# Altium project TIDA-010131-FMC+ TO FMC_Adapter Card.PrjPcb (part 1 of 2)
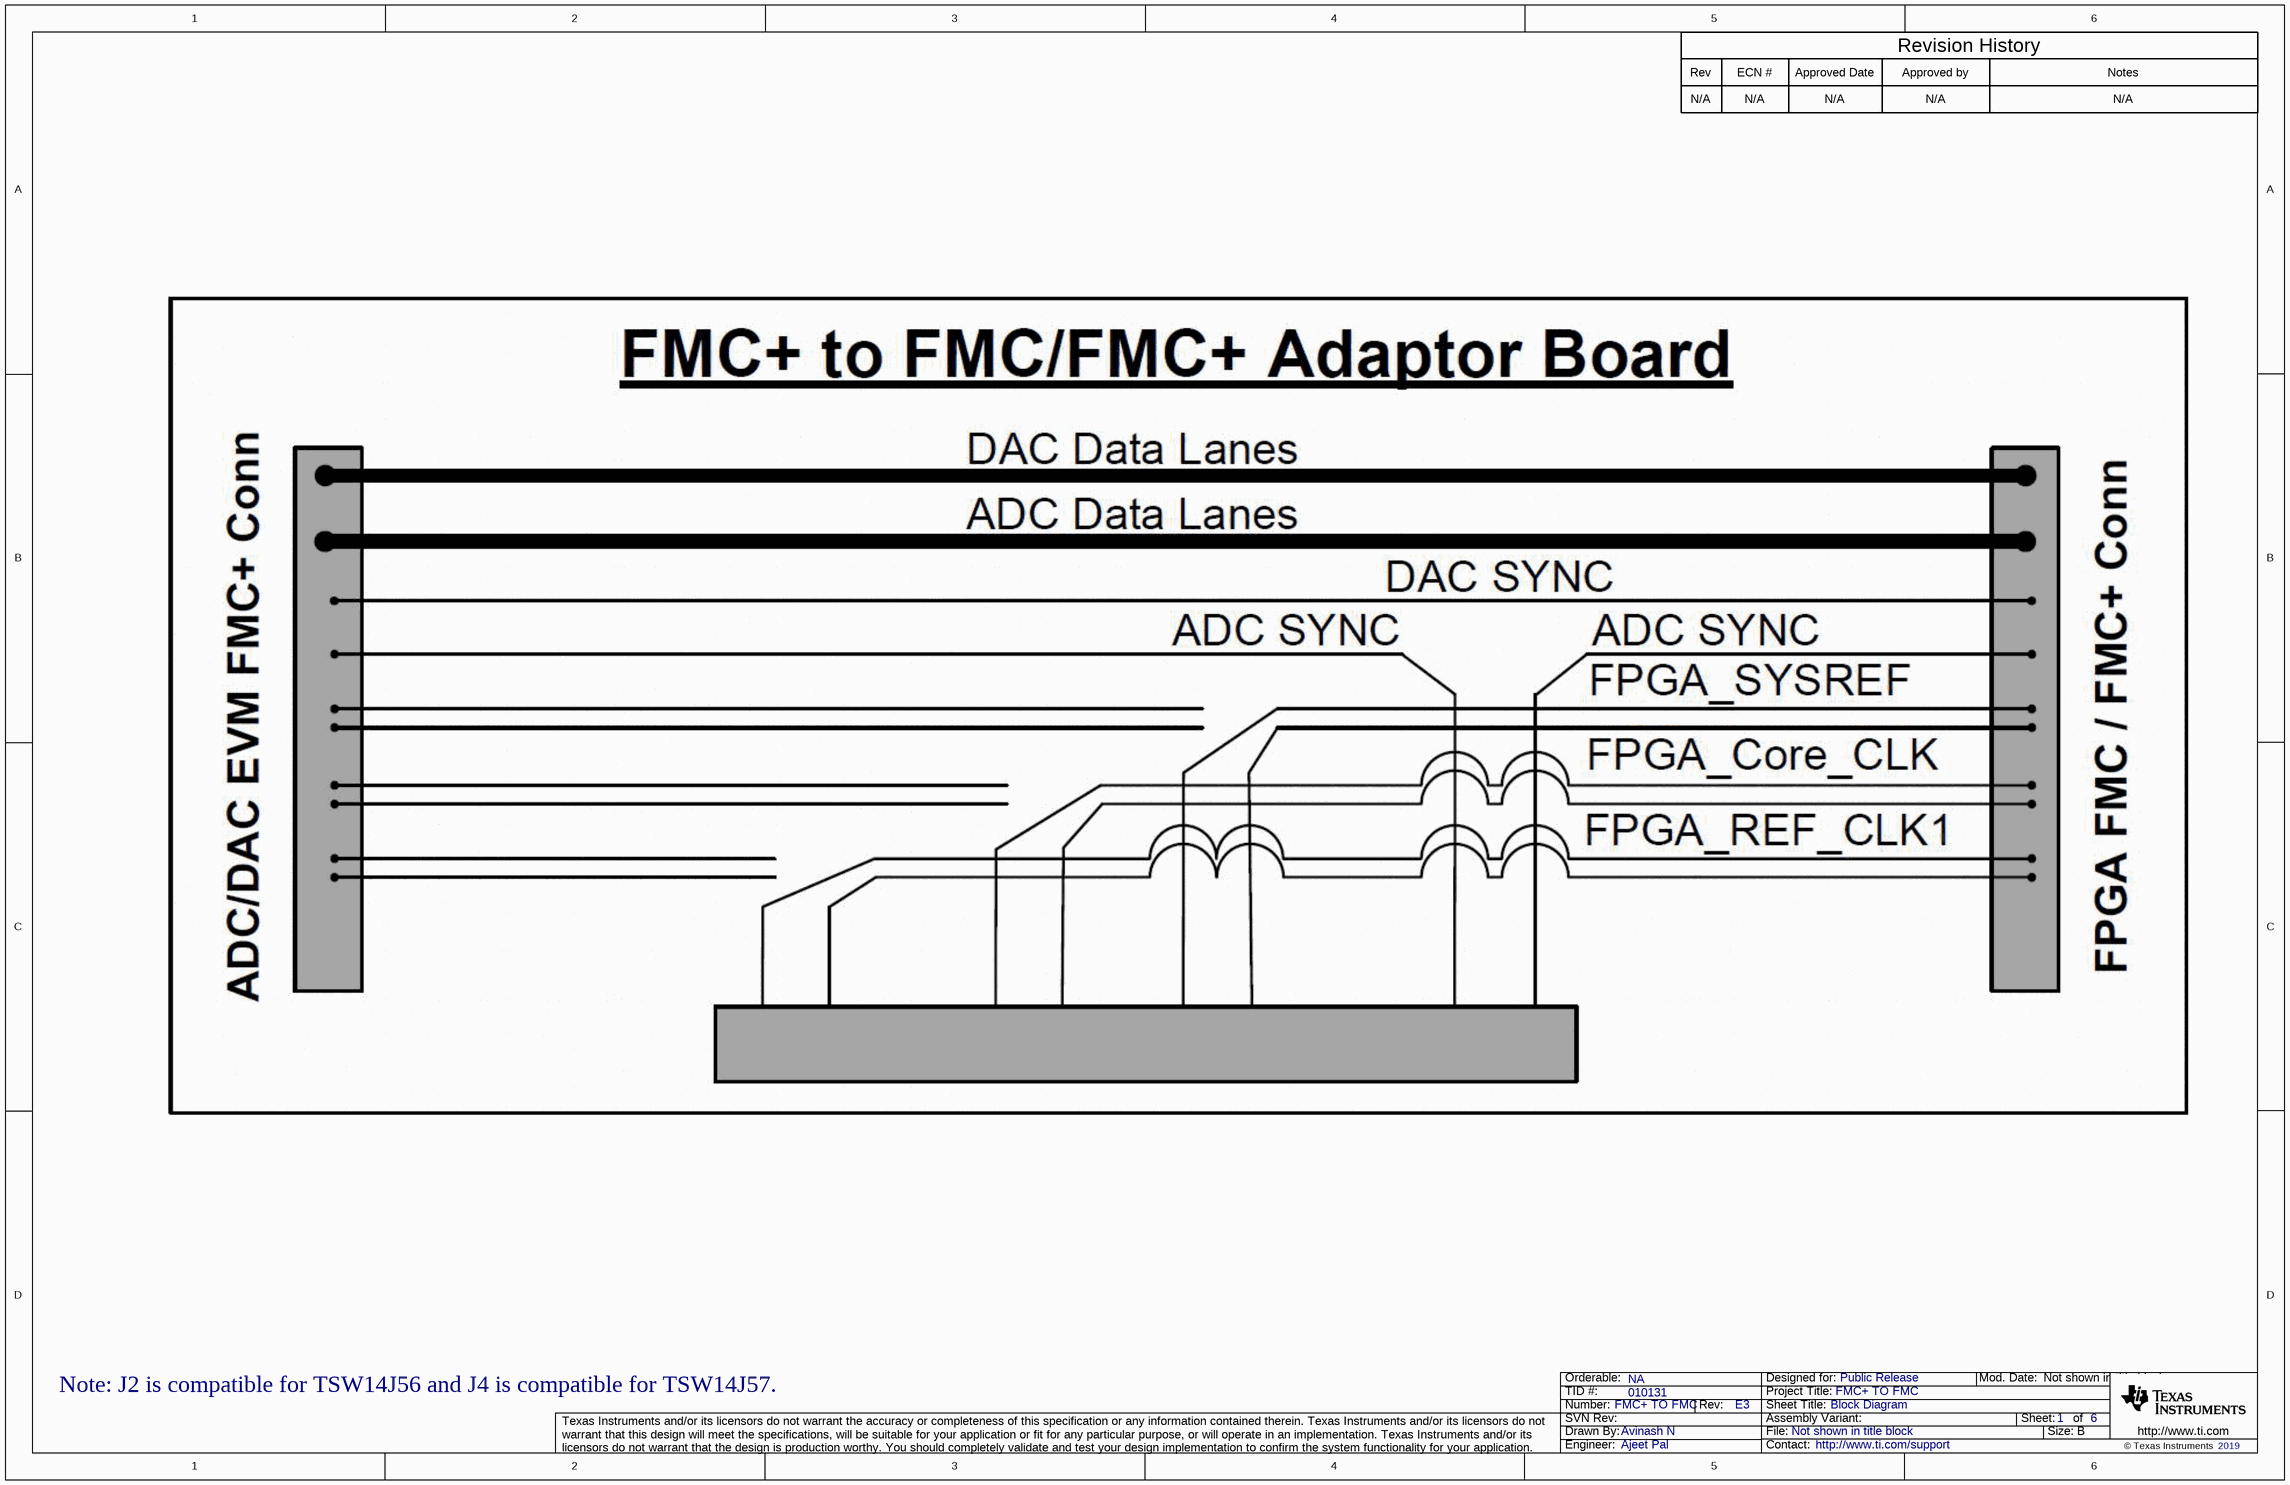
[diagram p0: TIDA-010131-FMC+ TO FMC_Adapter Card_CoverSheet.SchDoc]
CopyrightYear: 2019; EVM_orderable: NA; PCB_Layout: Avinash N; PCB_Rev: E3; PRJ_Customer: Public Release; PRJ_Engineer: Ajeet Pal; PRJ_Number: FMC+ TO FMC; PRJ_Title: FMC+ TO FMC; SCH_Rev: E3; TechSupport: http://www.ti.com/support; TID: 010131
6 sheets, 65 parts. Net scope: global (net labels, ports and power ports of the same name join across sheets).
Board file: TIDA-010131-FMC+ TO FMC_Adapter Card.PcbDoc
Sheets:
  TIDA-010131-FMC+ TO FMC_Adapter Card_CoverSheet.SchDoc
  TIDA-010131-FMC+ TO FMC_Adapter Card_Sheet1.SchDoc
  TIDA-010131-FMC+ TO FMC_Adapter Card_Sheet2.SchDoc
  TIDA-010131-FMC+ TO FMC_Adapter Card_Sheet3.SchDoc
  TIDA-010131-FMC+ TO FMC_Adapter Card_Sheet4.SchDoc
  TIDA-010131-FMC+ TO FMC_Adapter Card_Hardware.SchDoc

## Sheet TIDA-010131-FMC+ TO FMC_Adapter Card_CoverSheet.SchDoc: Block Diagram
size 431 x 279 mm; Date: Not shown in title block; ApprovedBy: Not shown in title block; CheckedBy: Not shown in title block; Author: Not shown in title block; CompanyName: Not shown in title block; DrawnBy: Avinash N; Engineer: Not shown in title block; Organization: Not shown in title block; Address1: Not shown in title block; Address2: Not shown in title block; Address3: Not shown in title block; Address4: Not shown in title block; DocumentNumber: 1; Revision: Use project parameter SCH_Rev; SheetNumber: 1; SheetTotal: 6; PageSetup: Record=PageOptions¦CenterHorizontal=True¦CenterVertical=True¦PrintScale=1.00¦XCorrection=1.00¦YCorrection=1.00¦PrintKind=0¦BorderSize=5000000¦LeftOffset=0¦BottomOffset=0¦Orientation=2¦PaperLength=1000¦PaperWidth=1000¦Scale=100¦PaperSource=15¦PrintQuality=600¦MediaType=1¦DitherType=10¦PaperKind=Letter¦PrintScaleMode=1

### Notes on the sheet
- Rev
- N/A
- ECN #
- Approved Date
- Approved by
- Revision History
- Notes
- Note: J2 is compatible for TSW14J56 and J4 is compatible for TSW14J57.

## Sheet TIDA-010131-FMC+ TO FMC_Adapter Card_Sheet1.SchDoc
size 431 x 279 mm; Date: Not shown in title block; ApprovedBy: Not shown in title block; CheckedBy: Not shown in title block; Author: Not shown in title block; CompanyName: Not shown in title block; DrawnBy: Avinash N; Engineer: Not shown in title block; Organization: Not shown in title block; Address1: Not shown in title block; Address2: Not shown in title block; Address3: Not shown in title block; Address4: Not shown in title block; DocumentNumber: 2; Revision: Use project parameter SCH_Rev; SheetNumber: 2; SheetTotal: 6; PageSetup: Record=PageOptions¦CenterHorizontal=True¦CenterVertical=True¦PrintScale=1.00¦XCorrection=1.00¦YCorrection=1.00¦PrintKind=0¦BorderSize=5000000¦LeftOffset=0¦BottomOffset=0¦Orientation=2¦PaperLength=1000¦PaperWidth=1000¦Scale=100¦PaperSource=15¦PrintQuality=600¦MediaType=1¦DitherType=10¦PaperKind=Letter¦PrintScaleMode=1
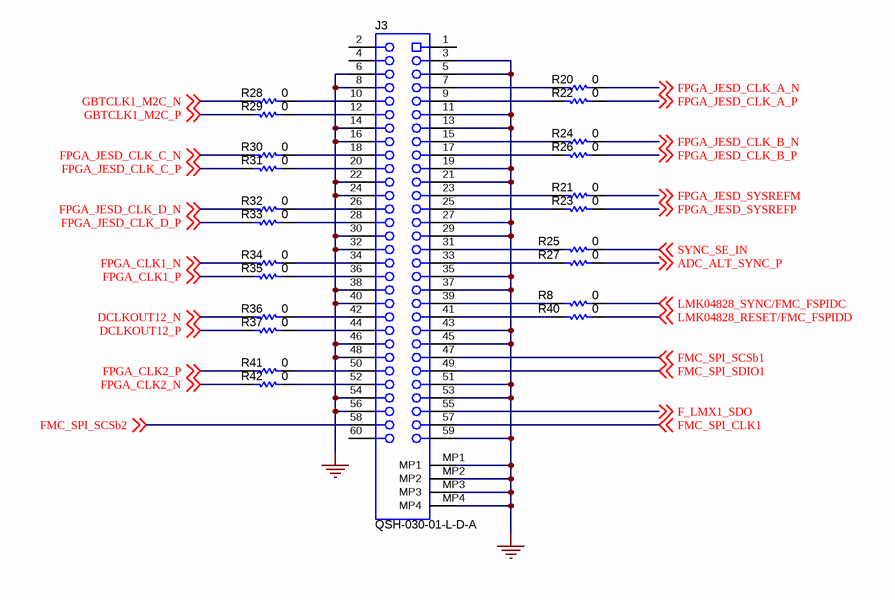
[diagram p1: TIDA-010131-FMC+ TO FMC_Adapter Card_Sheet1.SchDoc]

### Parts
J3  QSH-030-01-L-D-A  [Samtec_QSH-030-01-X-D-A]
R8  ValueDisplayed: 0  [0402]  (hidden comment: CRCW04020000Z0ED)
R20  ValueDisplayed: 0  [0201]  (hidden comment: ERJ-1GN0R00C)
R21  ValueDisplayed: 0  [0201]  (hidden comment: ERJ-1GN0R00C)
R22  ValueDisplayed: 0  [0201]  (hidden comment: ERJ-1GN0R00C)
R23  ValueDisplayed: 0  [0201]  (hidden comment: ERJ-1GN0R00C)
R24  ValueDisplayed: 0  [0201]  (hidden comment: ERJ-1GN0R00C)
R25  ValueDisplayed: 0  [0402]  (hidden comment: CRCW04020000Z0ED)
R26  ValueDisplayed: 0  [0201]  (hidden comment: ERJ-1GN0R00C)
R27  ValueDisplayed: 0  [0402]  (hidden comment: CRCW04020000Z0ED)
R28  ValueDisplayed: 0  [0201]  (hidden comment: ERJ-1GN0R00C)
R29  ValueDisplayed: 0  [0201]  (hidden comment: ERJ-1GN0R00C)
R30  ValueDisplayed: 0  [0201]  (hidden comment: ERJ-1GN0R00C)
R31  ValueDisplayed: 0  [0201]  (hidden comment: ERJ-1GN0R00C)
R32  ValueDisplayed: 0  [0201]  (hidden comment: ERJ-1GN0R00C)
R33  ValueDisplayed: 0  [0201]  (hidden comment: ERJ-1GN0R00C)
R34  ValueDisplayed: 0  [0201]  (hidden comment: ERJ-1GN0R00C)
R35  ValueDisplayed: 0  [0201]  (hidden comment: ERJ-1GN0R00C)
R36  ValueDisplayed: 0  [0201]  (hidden comment: ERJ-1GN0R00C)
R37  ValueDisplayed: 0  [0201]  (hidden comment: ERJ-1GN0R00C)
R40  ValueDisplayed: 0  [0402]  (hidden comment: CRCW04020000Z0ED)
R41  ValueDisplayed: 0  [0201]  (hidden comment: ERJ-1GN0R00C)
R42  ValueDisplayed: 0  [0201]  (hidden comment: ERJ-1GN0R00C)

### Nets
GND: J3.3 J3.5 J3.6 J3.8 J3.11 J3.13 J3.14 J3.16 J3.19 J3.21 J3.22 J3.24 J3.27 J3.29 J3.30 J3.32 J3.35 J3.37 J3.38 J3.40 J3.43 J3.45 J3.46 J3.48 J3.51 J3.53 J3.54 J3.56 J3.59 J3.MP1 J3.MP2 J3.MP3 J3.MP4
ADC_ALT_SYNC_P: R27.1 ; off-sheet ADC_ALT_SYNC_P
DCLKOUT12_N: R36.2 ; off-sheet DCLKOUT12_N
DCLKOUT12_P: R37.2 ; off-sheet DCLKOUT12_P
F_LMX1_SDO: J3.55 ; off-sheet F_LMX1_SDO
FMC_SPI_CLK1: J3.57 ; off-sheet FMC_SPI_CLK1
FMC_SPI_SCSb1: J3.47 ; off-sheet FMC_SPI_SCSb1
FMC_SPI_SCSb2: J3.58 ; off-sheet FMC_SPI_SCSb2
FMC_SPI_SDIO1: J3.49 ; off-sheet FMC_SPI_SDIO1
FPGA_CLK1_N: R34.2 ; off-sheet FPGA_CLK1_N
FPGA_CLK1_P: R35.2 ; off-sheet FPGA_CLK1_P
FPGA_CLK2_N: R42.2 ; off-sheet FPGA_CLK2_N
FPGA_CLK2_P: R41.2 ; off-sheet FPGA_CLK2_P
FPGA_JESD_CLK_A_N: R20.1 ; off-sheet FPGA_JESD_CLK_A_N
FPGA_JESD_CLK_A_P: R22.1 ; off-sheet FPGA_JESD_CLK_A_P
FPGA_JESD_CLK_B_N: R24.1 ; off-sheet FPGA_JESD_CLK_B_N
FPGA_JESD_CLK_B_P: R26.1 ; off-sheet FPGA_JESD_CLK_B_P
FPGA_JESD_CLK_C_N: R30.2 ; off-sheet FPGA_JESD_CLK_C_N
FPGA_JESD_CLK_C_P: R31.2 ; off-sheet FPGA_JESD_CLK_C_P
FPGA_JESD_CLK_D_N: R32.2 ; off-sheet FPGA_JESD_CLK_D_N
FPGA_JESD_CLK_D_P: R33.2 ; off-sheet FPGA_JESD_CLK_D_P
FPGA_JESD_SYSREFM: R21.1 ; off-sheet FPGA_JESD_SYSREFM
FPGA_JESD_SYSREFP: R23.1 ; off-sheet FPGA_JESD_SYSREFP
GBTCLK1_M2C_N: R28.2 ; off-sheet GBTCLK1_M2C_N
GBTCLK1_M2C_P: R29.2 ; off-sheet GBTCLK1_M2C_P
LMK04828_RESET/FMC_FSPIDD: R40.1 ; off-sheet LMK04828_RESET/FMC_FSPIDD
LMK04828_SYNC/FMC_FSPIDC: R8.1 ; off-sheet LMK04828_SYNC/FMC_FSPIDC
SYNC_SE_IN: R25.1 ; off-sheet SYNC_SE_IN
NetJ3_7: J3.7 R20.2
NetJ3_9: J3.9 R22.2
NetJ3_10: J3.10 R28.1
NetJ3_12: J3.12 R29.1
NetJ3_15: J3.15 R24.2
NetJ3_17: J3.17 R26.2
NetJ3_18: J3.18 R30.1
NetJ3_20: J3.20 R31.1
NetJ3_23: J3.23 R21.2
NetJ3_25: J3.25 R23.2
NetJ3_26: J3.26 R32.1
NetJ3_28: J3.28 R33.1
NetJ3_31: J3.31 R25.2
NetJ3_33: J3.33 R27.2
NetJ3_34: J3.34 R34.1
NetJ3_36: J3.36 R35.1
NetJ3_39: J3.39 R8.2
NetJ3_41: J3.41 R40.2
NetJ3_42: J3.42 R36.1
NetJ3_44: J3.44 R37.1
NetJ3_50: J3.50 R41.1
NetJ3_52: J3.52 R42.1

Not connected (* = marked no-connect by the designer): J3 1 2 4 60

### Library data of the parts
J3 = QSH-030-01-L-D-A: Receptacle, 0.5 mm, 30x2, Gold, TH; Manufacturer: Samtec; SymbolCreator: Altium; Pitch_mm: 0.5; Gender: Female; Shrouded: N; Row_Count: 2; RowSpacing_mm: 5.73
R8 R25 R27 R40 = CRCW04020000Z0ED: RES, 0, 5%, 0.063 W, 0402; Manufacturer: Vishay-Dale; CompType: Resistor; Value: 0; Value_Code: 0000; Tolerance_%: 5; Power_W: 0.063; Value2: 0.063W; VDC_V: 50; TempCo: 200 ppm/C; SizeArea_mm2: 0.5; SizeX_mm: 1; SizeZ_mm: 0.6; EIA_Code: E24; U/M: EA; AEC Category: Q200
R20-R24 R26 R28-R37 R41 R42 = ERJ-1GN0R00C: RES, 0, 5%, 0.05 W, AEC-Q200 Grade 0, 0201; Manufacturer: Panasonic; CompType: Resistor; Value: 0; Value_Code: 0000; Tolerance_%: 5; Power_W: 0.05; Value2: 0.05W; TempCo: ppm/C; SizeArea_mm2: 0.18; SizeX_mm: 0.6; SizeY_mm: 0.3; SizeZ_mm: 0.26; EIA_Code: E24; U/M: EA; AEC Category: Q200; AEC Qualified: Y

## Sheet TIDA-010131-FMC+ TO FMC_Adapter Card_Sheet2.SchDoc
size 431 x 279 mm; Date: Not shown in title block; ApprovedBy: Not shown in title block; CheckedBy: Not shown in title block; Author: Not shown in title block; CompanyName: Not shown in title block; DrawnBy: Avinash N; Engineer: Not shown in title block; Organization: Not shown in title block; Address1: Not shown in title block; Address2: Not shown in title block; Address3: Not shown in title block; Address4: Not shown in title block; DocumentNumber: 3; Revision: Use project parameter SCH_Rev; SheetNumber: 3; SheetTotal: 6; PageSetup: Record=PageOptions¦CenterHorizontal=True¦CenterVertical=True¦PrintScale=0.64¦XCorrection=1.00¦YCorrection=1.00¦PrintKind=0¦BorderSize=5000000¦LeftOffset=0¦BottomOffset=0¦Orientation=2¦PaperLength=1000¦PaperWidth=1000¦Scale=100¦PaperSource=15¦PrintQuality=600¦MediaType=1¦DitherType=10¦PrintScaleMode=1¦PaperKind=Letter
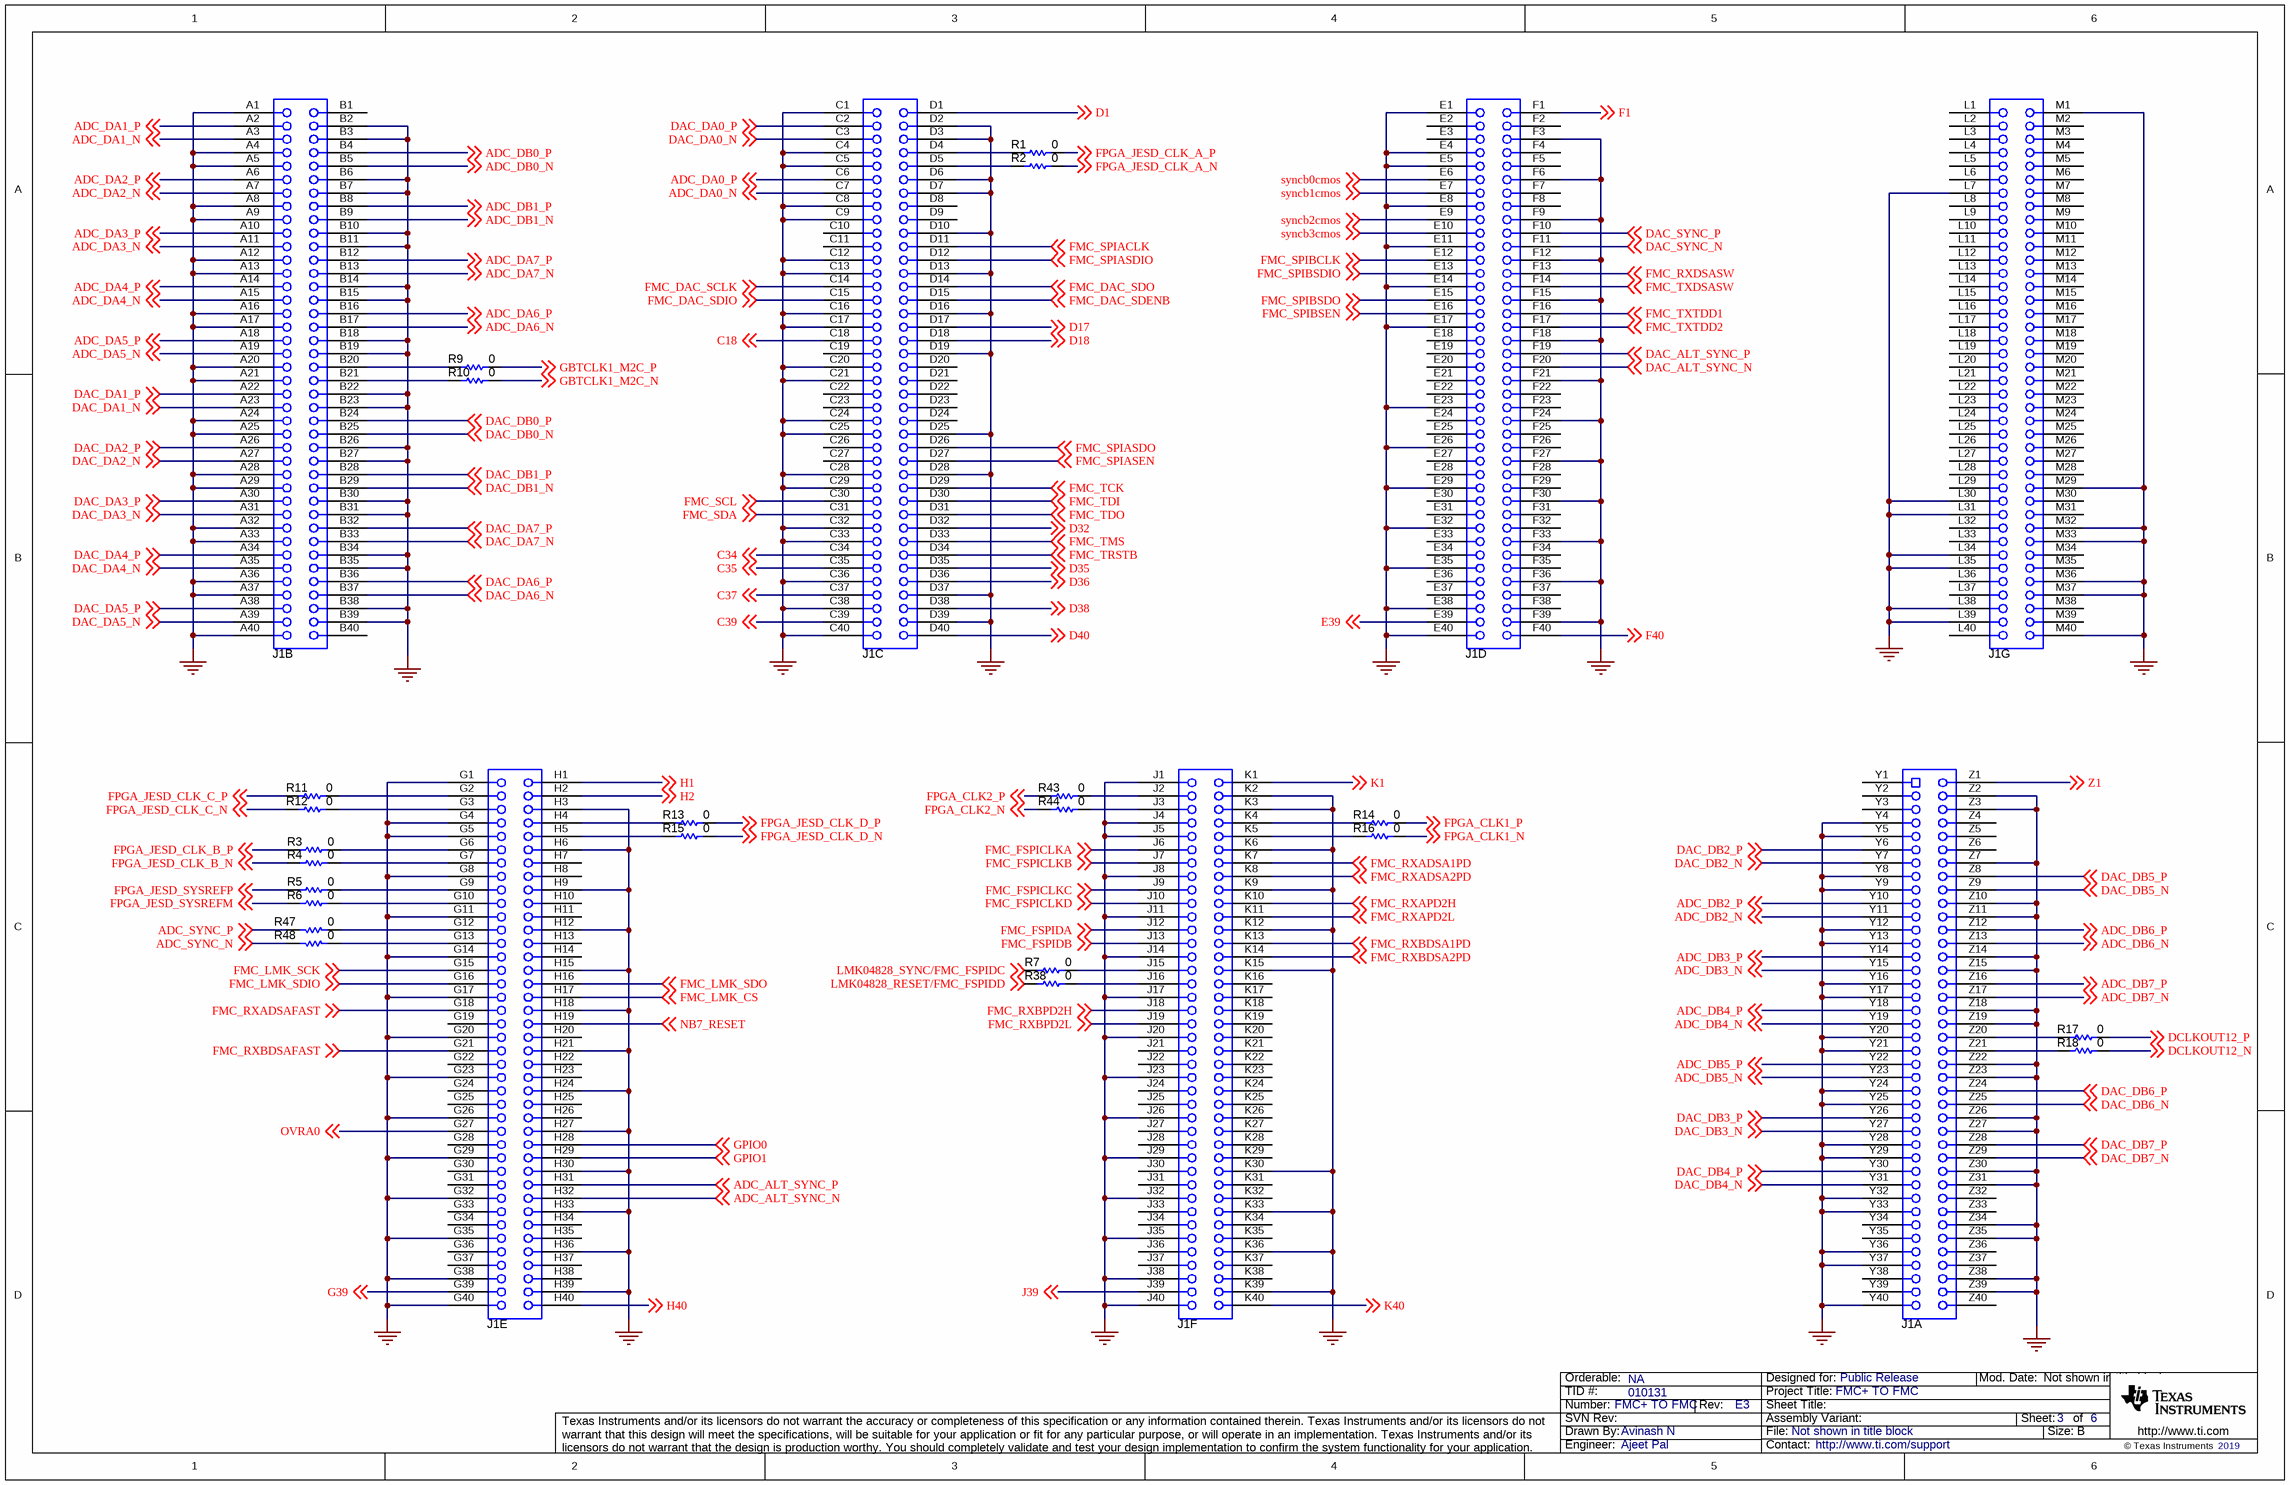
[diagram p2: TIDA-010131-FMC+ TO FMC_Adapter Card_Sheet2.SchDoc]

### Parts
J1  ASP-184329-01  [Samtec_ASP-184329-01]  (value not drawn)  (parts A,B,C,D,E,F,G of 7)
R1  ValueDisplayed: 0  [0201]  (hidden comment: ERJ-1GN0R00C)
R2  ValueDisplayed: 0  [0201]  (hidden comment: ERJ-1GN0R00C)
R3  ValueDisplayed: 0  [0201]  (hidden comment: ERJ-1GN0R00C)
R4  ValueDisplayed: 0  [0201]  (hidden comment: ERJ-1GN0R00C)
R5  ValueDisplayed: 0  [0201]  (hidden comment: ERJ-1GN0R00C)
R6  ValueDisplayed: 0  [0201]  (hidden comment: ERJ-1GN0R00C)
R7  ValueDisplayed: 0  [0402]  (hidden comment: CRCW04020000Z0ED)
R9  ValueDisplayed: 0  [0201]  (hidden comment: ERJ-1GN0R00C)
R10  ValueDisplayed: 0  [0201]  (hidden comment: ERJ-1GN0R00C)
R11  ValueDisplayed: 0  [0201]  (hidden comment: ERJ-1GN0R00C)
R12  ValueDisplayed: 0  [0201]  (hidden comment: ERJ-1GN0R00C)
R13  ValueDisplayed: 0  [0201]  (hidden comment: ERJ-1GN0R00C)
R14  ValueDisplayed: 0  [0201]  (hidden comment: ERJ-1GN0R00C)
R15  ValueDisplayed: 0  [0201]  (hidden comment: ERJ-1GN0R00C)
R16  ValueDisplayed: 0  [0201]  (hidden comment: ERJ-1GN0R00C)
R17  ValueDisplayed: 0  [0201]  (hidden comment: ERJ-1GN0R00C)
R18  ValueDisplayed: 0  [0201]  (hidden comment: ERJ-1GN0R00C)
R38  ValueDisplayed: 0  [0402]  (hidden comment: CRCW04020000Z0ED)
R43  ValueDisplayed: 0  [0201]  (hidden comment: ERJ-1GN0R00C)
R44  ValueDisplayed: 0  [0201]  (hidden comment: ERJ-1GN0R00C)
R47  ValueDisplayed: 0  [0402]  (hidden comment: CRCW04020000Z0ED)
R48  ValueDisplayed: 0  [0402]  (hidden comment: CRCW04020000Z0ED)

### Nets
GND: J1.A1 J1.A4 J1.A5 J1.A8 J1.A9 J1.A12 J1.A13 J1.A16 J1.A17 J1.A20 J1.A21 J1.A24 J1.A25 J1.A28 J1.A29 J1.A32 J1.A33 J1.A36 J1.A37 J1.A40 J1.B2 J1.B3 J1.B6 J1.B7 J1.B10 J1.B11 J1.B14 J1.B15 J1.B18 J1.B19 J1.B22 J1.B23 J1.B26 J1.B27 J1.B30 J1.B31 J1.B34 J1.B35 J1.B38 J1.B39 J1.C1 J1.C4 J1.C5 J1.C8 J1.C9 J1.C12 J1.C13 J1.C16 J1.C17 J1.C20 J1.C21 J1.C24 J1.C25 J1.C28 J1.C29 J1.C32 J1.C33 J1.C36 J1.C38 J1.C40 J1.D2 J1.D3 J1.D6 J1.D7 J1.D10 J1.D13 J1.D16 J1.D19 J1.D25 J1.D28 J1.D37 J1.D39 J1.E1 J1.E4 J1.E5 J1.E8 J1.E11 J1.E14 J1.E17 J1.E23 J1.E26 J1.E29 J1.E32 J1.E35 J1.E38 J1.E40 J1.F3 J1.F6 J1.F9 J1.F12 J1.F15 J1.F18 J1.F21 J1.F24 J1.F27 J1.F30 J1.F33 J1.F36 J1.F39 J1.G1 J1.G4 J1.G5 J1.G8 J1.G11 J1.G14 J1.G17 J1.G20 J1.G23 J1.G26 J1.G29 J1.G32 J1.G35 J1.G38 J1.G40 J1.H3 J1.H6 J1.H9 J1.H12 J1.H15 J1.H18 J1.H21 J1.H24 J1.H27 J1.H30 J1.H33 J1.H36 J1.H39 J1.J1 J1.J4 J1.J5 J1.J8 J1.J11 J1.J14 J1.J17 J1.J20 J1.J23 J1.J26 J1.J29 J1.J32 J1.J35 J1.J38 J1.J40 J1.K2 J1.K3 J1.K6 J1.K9 J1.K12 J1.K15 J1.K30 J1.K33 J1.K36 J1.K39 J1.L7 J1.L30 J1.L31 J1.L34 J1.L35 J1.L38 J1.L39 J1.M1 J1.M29 J1.M32 J1.M33 J1.M36 J1.M37 J1.M40 J1.Y4 J1.Y5 J1.Y8 J1.Y9 J1.Y12 J1.Y13 J1.Y16 J1.Y17 J1.Y20 J1.Y21 J1.Y24 J1.Y25 J1.Y28 J1.Y29 J1.Y32 J1.Y33 J1.Y36 J1.Y37 J1.Y40 J1.Z2 J1.Z3 J1.Z7 J1.Z10 J1.Z11 J1.Z14 J1.Z15 J1.Z18 J1.Z19 J1.Z22 J1.Z23 J1.Z26 J1.Z27 J1.Z30 J1.Z31 J1.Z34 J1.Z35 J1.Z38 J1.Z39
ADC_ALT_SYNC_N: J1.H32 ; off-sheet ADC_ALT_SYNC_N
ADC_ALT_SYNC_P: J1.H31 ; off-sheet ADC_ALT_SYNC_P
ADC_DA0_N: J1.C7 ; off-sheet ADC_DA0_N
ADC_DA0_P: J1.C6 ; off-sheet ADC_DA0_P
ADC_DA1_N: J1.A3 ; off-sheet ADC_DA1_N
ADC_DA1_P: J1.A2 ; off-sheet ADC_DA1_P
ADC_DA2_N: J1.A7 ; off-sheet ADC_DA2_N
ADC_DA2_P: J1.A6 ; off-sheet ADC_DA2_P
ADC_DA3_N: J1.A11 ; off-sheet ADC_DA3_N
ADC_DA3_P: J1.A10 ; off-sheet ADC_DA3_P
ADC_DA4_N: J1.A15 ; off-sheet ADC_DA4_N
ADC_DA4_P: J1.A14 ; off-sheet ADC_DA4_P
ADC_DA5_N: J1.A19 ; off-sheet ADC_DA5_N
ADC_DA5_P: J1.A18 ; off-sheet ADC_DA5_P
ADC_DA6_N: J1.B17 ; off-sheet ADC_DA6_N
ADC_DA6_P: J1.B16 ; off-sheet ADC_DA6_P
ADC_DA7_N: J1.B13 ; off-sheet ADC_DA7_N
ADC_DA7_P: J1.B12 ; off-sheet ADC_DA7_P
ADC_DB0_N: J1.B5 ; off-sheet ADC_DB0_N
ADC_DB0_P: J1.B4 ; off-sheet ADC_DB0_P
ADC_DB1_N: J1.B9 ; off-sheet ADC_DB1_N
ADC_DB1_P: J1.B8 ; off-sheet ADC_DB1_P
ADC_DB2_N: J1.Y11 ; off-sheet ADC_DB2_N
ADC_DB2_P: J1.Y10 ; off-sheet ADC_DB2_P
ADC_DB3_N: J1.Y15 ; off-sheet ADC_DB3_N
ADC_DB3_P: J1.Y14 ; off-sheet ADC_DB3_P
ADC_DB4_N: J1.Y19 ; off-sheet ADC_DB4_N
ADC_DB4_P: J1.Y18 ; off-sheet ADC_DB4_P
ADC_DB5_N: J1.Y23 ; off-sheet ADC_DB5_N
ADC_DB5_P: J1.Y22 ; off-sheet ADC_DB5_P
ADC_DB6_N: J1.Z13 ; off-sheet ADC_DB6_N
ADC_DB6_P: J1.Z12 ; off-sheet ADC_DB6_P
ADC_DB7_N: J1.Z17 ; off-sheet ADC_DB7_N
ADC_DB7_P: J1.Z16 ; off-sheet ADC_DB7_P
ADC_SYNC_N: R48.2 ; off-sheet ADC_SYNC_N
ADC_SYNC_P: R47.2 ; off-sheet ADC_SYNC_P
C18: J1.C18 ; off-sheet C18
C34: J1.C34 ; off-sheet C34
C35: J1.C35 ; off-sheet C35
C37: J1.C37 ; off-sheet C37
C39: J1.C39 ; off-sheet C39
D1: J1.D1 ; off-sheet D1
D17: J1.D17 ; off-sheet D17
D18: J1.D18 ; off-sheet D18
D32: J1.D32 ; off-sheet D32
D35: J1.D35 ; off-sheet D35
D36: J1.D36 ; off-sheet D36
D38: J1.D38 ; off-sheet D38
D40: J1.D40 ; off-sheet D40
DAC_ALT_SYNC_N: J1.F20 ; off-sheet DAC_ALT_SYNC_N
DAC_ALT_SYNC_P: J1.F19 ; off-sheet DAC_ALT_SYNC_P
DAC_DA0_N: J1.C3 ; off-sheet DAC_DA0_N
DAC_DA0_P: J1.C2 ; off-sheet DAC_DA0_P
DAC_DA1_N: J1.A23 ; off-sheet DAC_DA1_N
DAC_DA1_P: J1.A22 ; off-sheet DAC_DA1_P
DAC_DA2_N: J1.A27 ; off-sheet DAC_DA2_N
DAC_DA2_P: J1.A26 ; off-sheet DAC_DA2_P
DAC_DA3_N: J1.A31 ; off-sheet DAC_DA3_N
DAC_DA3_P: J1.A30 ; off-sheet DAC_DA3_P
DAC_DA4_N: J1.A35 ; off-sheet DAC_DA4_N
DAC_DA4_P: J1.A34 ; off-sheet DAC_DA4_P
DAC_DA5_N: J1.A39 ; off-sheet DAC_DA5_N
DAC_DA5_P: J1.A38 ; off-sheet DAC_DA5_P
DAC_DA6_N: J1.B37 ; off-sheet DAC_DA6_N
DAC_DA6_P: J1.B36 ; off-sheet DAC_DA6_P
DAC_DA7_N: J1.B33 ; off-sheet DAC_DA7_N
DAC_DA7_P: J1.B32 ; off-sheet DAC_DA7_P
DAC_DB0_N: J1.B25 ; off-sheet DAC_DB0_N
DAC_DB0_P: J1.B24 ; off-sheet DAC_DB0_P
DAC_DB1_N: J1.B29 ; off-sheet DAC_DB1_N
DAC_DB1_P: J1.B28 ; off-sheet DAC_DB1_P
DAC_DB2_N: J1.Y7 ; off-sheet DAC_DB2_N
DAC_DB2_P: J1.Y6 ; off-sheet DAC_DB2_P
DAC_DB3_N: J1.Y27 ; off-sheet DAC_DB3_N
DAC_DB3_P: J1.Y26 ; off-sheet DAC_DB3_P
DAC_DB4_N: J1.Y31 ; off-sheet DAC_DB4_N
DAC_DB4_P: J1.Y30 ; off-sheet DAC_DB4_P
DAC_DB5_N: J1.Z9 ; off-sheet DAC_DB5_N
DAC_DB5_P: J1.Z8 ; off-sheet DAC_DB5_P
DAC_DB6_N: J1.Z25 ; off-sheet DAC_DB6_N
DAC_DB6_P: J1.Z24 ; off-sheet DAC_DB6_P
DAC_DB7_N: J1.Z29 ; off-sheet DAC_DB7_N
DAC_DB7_P: J1.Z28 ; off-sheet DAC_DB7_P
DAC_SYNC_N: J1.F11 ; off-sheet DAC_SYNC_N
DAC_SYNC_P: J1.F10 ; off-sheet DAC_SYNC_P
DCLKOUT12_N: R18.1 ; off-sheet DCLKOUT12_N
DCLKOUT12_P: R17.1 ; off-sheet DCLKOUT12_P
E39: J1.E39 ; off-sheet E39
F1: J1.F1 ; off-sheet F1
F40: J1.F40 ; off-sheet F40
FMC_DAC_SCLK: J1.C14 ; off-sheet FMC_DAC_SCLK
FMC_DAC_SDENB: J1.D15 ; off-sheet FMC_DAC_SDENB
FMC_DAC_SDIO: J1.C15 ; off-sheet FMC_DAC_SDIO
FMC_DAC_SDO: J1.D14 ; off-sheet FMC_DAC_SDO
FMC_FSPICLKA: J1.J6 ; off-sheet FMC_FSPICLKA
FMC_FSPICLKB: J1.J7 ; off-sheet FMC_FSPICLKB
FMC_FSPICLKC: J1.J9 ; off-sheet FMC_FSPICLKC
FMC_FSPICLKD: J1.J10 ; off-sheet FMC_FSPICLKD
FMC_FSPIDA: J1.J12 ; off-sheet FMC_FSPIDA
FMC_FSPIDB: J1.J13 ; off-sheet FMC_FSPIDB
FMC_LMK_CS: J1.H17 ; off-sheet FMC_LMK_CS
FMC_LMK_SCK: J1.G15 ; off-sheet FMC_LMK_SCK
FMC_LMK_SDIO: J1.G16 ; off-sheet FMC_LMK_SDIO
FMC_LMK_SDO: J1.H16 ; off-sheet FMC_LMK_SDO
FMC_RXADSA1PD: J1.K7 ; off-sheet FMC_RXADSA1PD
FMC_RXADSA2PD: J1.K8 ; off-sheet FMC_RXADSA2PD
FMC_RXADSAFAST: J1.G18 ; off-sheet FMC_RXADSAFAST
FMC_RXAPD2H: J1.K10 ; off-sheet FMC_RXAPD2H
FMC_RXAPD2L: J1.K11 ; off-sheet FMC_RXAPD2L
FMC_RXBDSA1PD: J1.K13 ; off-sheet FMC_RXBDSA1PD
FMC_RXBDSA2PD: J1.K14 ; off-sheet FMC_RXBDSA2PD
FMC_RXBDSAFAST: J1.G21 ; off-sheet FMC_RXBDSAFAST
FMC_RXBPD2H: J1.J18 ; off-sheet FMC_RXBPD2H
FMC_RXBPD2L: J1.J19 ; off-sheet FMC_RXBPD2L
FMC_RXDSASW: J1.F13 ; off-sheet FMC_RXDSASW
FMC_SCL: J1.C30 ; off-sheet FMC_SCL
FMC_SDA: J1.C31 ; off-sheet FMC_SDA
FMC_SPIACLK: J1.D11 ; off-sheet FMC_SPIACLK
FMC_SPIASDIO: J1.D12 ; off-sheet FMC_SPIASDIO
FMC_SPIASDO: J1.D26 ; off-sheet FMC_SPIASDO
FMC_SPIASEN: J1.D27 ; off-sheet FMC_SPIASEN
FMC_SPIBCLK: J1.E12 ; off-sheet FMC_SPIBCLK
FMC_SPIBSDIO: J1.E13 ; off-sheet FMC_SPIBSDIO
FMC_SPIBSDO: J1.E15 ; off-sheet FMC_SPIBSDO
FMC_SPIBSEN: J1.E16 ; off-sheet FMC_SPIBSEN
FMC_TCK: J1.D29 ; off-sheet FMC_TCK
FMC_TDI: J1.D30 ; off-sheet FMC_TDI
FMC_TDO: J1.D31 ; off-sheet FMC_TDO
FMC_TMS: J1.D33 ; off-sheet FMC_TMS
FMC_TRSTB: J1.D34 ; off-sheet FMC_TRSTB
FMC_TXDSASW: J1.F14 ; off-sheet FMC_TXDSASW
FMC_TXTDD1: J1.F16 ; off-sheet FMC_TXTDD1
FMC_TXTDD2: J1.F17 ; off-sheet FMC_TXTDD2
FPGA_CLK1_N: R16.1 ; off-sheet FPGA_CLK1_N
FPGA_CLK1_P: R14.1 ; off-sheet FPGA_CLK1_P
FPGA_CLK2_N: R44.2 ; off-sheet FPGA_CLK2_N
FPGA_CLK2_P: R43.2 ; off-sheet FPGA_CLK2_P
FPGA_JESD_CLK_A_N: R2.1 ; off-sheet FPGA_JESD_CLK_A_N
FPGA_JESD_CLK_A_P: R1.1 ; off-sheet FPGA_JESD_CLK_A_P
FPGA_JESD_CLK_B_N: R4.2 ; off-sheet FPGA_JESD_CLK_B_N
FPGA_JESD_CLK_B_P: R3.2 ; off-sheet FPGA_JESD_CLK_B_P
FPGA_JESD_CLK_C_N: R12.2 ; off-sheet FPGA_JESD_CLK_C_N
FPGA_JESD_CLK_C_P: R11.2 ; off-sheet FPGA_JESD_CLK_C_P
FPGA_JESD_CLK_D_N: R15.1 ; off-sheet FPGA_JESD_CLK_D_N
FPGA_JESD_CLK_D_P: R13.1 ; off-sheet FPGA_JESD_CLK_D_P
FPGA_JESD_SYSREFM: R6.2 ; off-sheet FPGA_JESD_SYSREFM
FPGA_JESD_SYSREFP: R5.2 ; off-sheet FPGA_JESD_SYSREFP
G39: J1.G39 ; off-sheet G39
GBTCLK1_M2C_N: R10.1 ; off-sheet GBTCLK1_M2C_N
GBTCLK1_M2C_P: R9.1 ; off-sheet GBTCLK1_M2C_P
GPIO0: J1.H28 ; off-sheet GPIO0
GPIO1: J1.H29 ; off-sheet GPIO1
H1: J1.H1 ; off-sheet H1
H2: J1.H2 ; off-sheet H2
H40: J1.H40 ; off-sheet H40
J39: J1.J39 ; off-sheet J39
K1: J1.K1 ; off-sheet K1
K40: J1.K40 ; off-sheet K40
LMK04828_RESET/FMC_FSPIDD: R38.2 ; off-sheet LMK04828_RESET/FMC_FSPIDD
LMK04828_SYNC/FMC_FSPIDC: R7.2 ; off-sheet LMK04828_SYNC/FMC_FSPIDC
NB7_RESET: J1.H19 ; off-sheet NB7_RESET
OVRA0: J1.G27 ; off-sheet OVRA0
syncb0cmos: J1.E6 ; off-sheet syncb0cmos
syncb1cmos: J1.E7 ; off-sheet syncb1cmos
syncb2cmos: J1.E9 ; off-sheet syncb2cmos
syncb3cmos: J1.E10 ; off-sheet syncb3cmos
Z1: J1.Z1 ; off-sheet Z1
NetJ1_B20: J1.B20 R9.2
NetJ1_B21: J1.B21 R10.2
NetJ1_D4: J1.D4 R1.2
NetJ1_D5: J1.D5 R2.2
NetJ1_G2: J1.G2 R11.1
NetJ1_G3: J1.G3 R12.1
NetJ1_G6: J1.G6 R3.1
NetJ1_G7: J1.G7 R4.1
NetJ1_G9: J1.G9 R5.1
NetJ1_G10: J1.G10 R6.1
NetJ1_G12: J1.G12 R47.1
NetJ1_G13: J1.G13 R48.1
NetJ1_H4: J1.H4 R13.2
NetJ1_H5: J1.H5 R15.2
NetJ1_J2: J1.J2 R43.1
NetJ1_J3: J1.J3 R44.1
NetJ1_J15: J1.J15 R7.1
NetJ1_J16: J1.J16 R38.1
NetJ1_K4: J1.K4 R14.2
NetJ1_K5: J1.K5 R16.2
NetJ1_Z20: J1.Z20 R17.2
NetJ1_Z21: J1.Z21 R18.2

Not connected (* = marked no-connect by the designer): J1 B1 B40 C10 C11 C19 C22 C23 C26 C27 D8 D9 D20 D21 D22 D23 D24 E2 E3 E18 E19 E20 E21 E22 E24 E25 E27 E28 E30 E31 E33 E34 E36 E37 F2 F4 F5 F7 F8 F22 F23 F25 F26 F28 F29 F31 F32 F34 F35 F37 F38 G19 G22 G24 G25 G28 G30 G31 G33 G34 G36 G37 H7 H8 H10 H11 H13 H14 H20 H22 H23 H25 H26 H34 H35 H37 H38 J21 J22 J24 J25 J27 J28 J30 J31 J33 J34 J36 J37 K16 K17 K18 K19 K20 K21 K22 K23 K24 K25 K26 K27 K28 K29 K31 K32 K34 K35 K37 K38 L1 L2 L3 L4 L5 L6 L8 L9 L10 L11 L12 L13 L14 L15 L16 L17 L18 L19 L20 L21 L22 L23 L24 L25 L26 L27 L28 L29 L32 L33 L36 L37 L40 M2 M3 M4 M5 M6 M7 M8 M9 M10 M11 M12 M13 M14 M15 M16 M17 M18 M19 M20 M21 M22 M23 M24 M25 M26 M27 M28 M30 M31 M34 M35 M38 M39 Y1 Y2 Y3 Y34 Y35 Y38 Y39 Z4 Z5 Z6 Z32 Z33 Z36 Z37 Z40

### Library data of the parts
J1 = ASP-184329-01: Socket, 50 mil, 40x14, Gold, SMT; Manufacturer: Samtec; SymbolCreator: Altium; Pitch_mm: 0.5; Gender: Female; Row_Count: 14
R1-R6 R9-R18 R43 R44 = ERJ-1GN0R00C: as R20 on sheet TIDA-010131-FMC+ TO FMC_Adapter Card_Sheet1
R7 R38 R47 R48 = CRCW04020000Z0ED: as R8 on sheet TIDA-010131-FMC+ TO FMC_Adapter Card_Sheet1

## Sheet TIDA-010131-FMC+ TO FMC_Adapter Card_Sheet3.SchDoc
size 431 x 279 mm; Date: Not shown in title block; ApprovedBy: Not shown in title block; CheckedBy: Not shown in title block; Author: Not shown in title block; CompanyName: Not shown in title block; DrawnBy: Avinash N; Engineer: Not shown in title block; Organization: Not shown in title block; Address1: Not shown in title block; Address2: Not shown in title block; Address3: Not shown in title block; Address4: Not shown in title block; DocumentNumber: 4; Revision: Use project parameter SCH_Rev; SheetNumber: 4; SheetTotal: 6; PageSetup: Record=PageOptions¦CenterHorizontal=True¦CenterVertical=True¦PrintScale=1.00¦XCorrection=1.00¦YCorrection=1.00¦PrintKind=0¦BorderSize=5000000¦LeftOffset=0¦BottomOffset=0¦Orientation=2¦PaperLength=1000¦PaperWidth=1000¦Scale=100¦PaperSource=15¦PrintQuality=600¦MediaType=1¦DitherType=10¦PaperKind=Letter¦PrintScaleMode=1
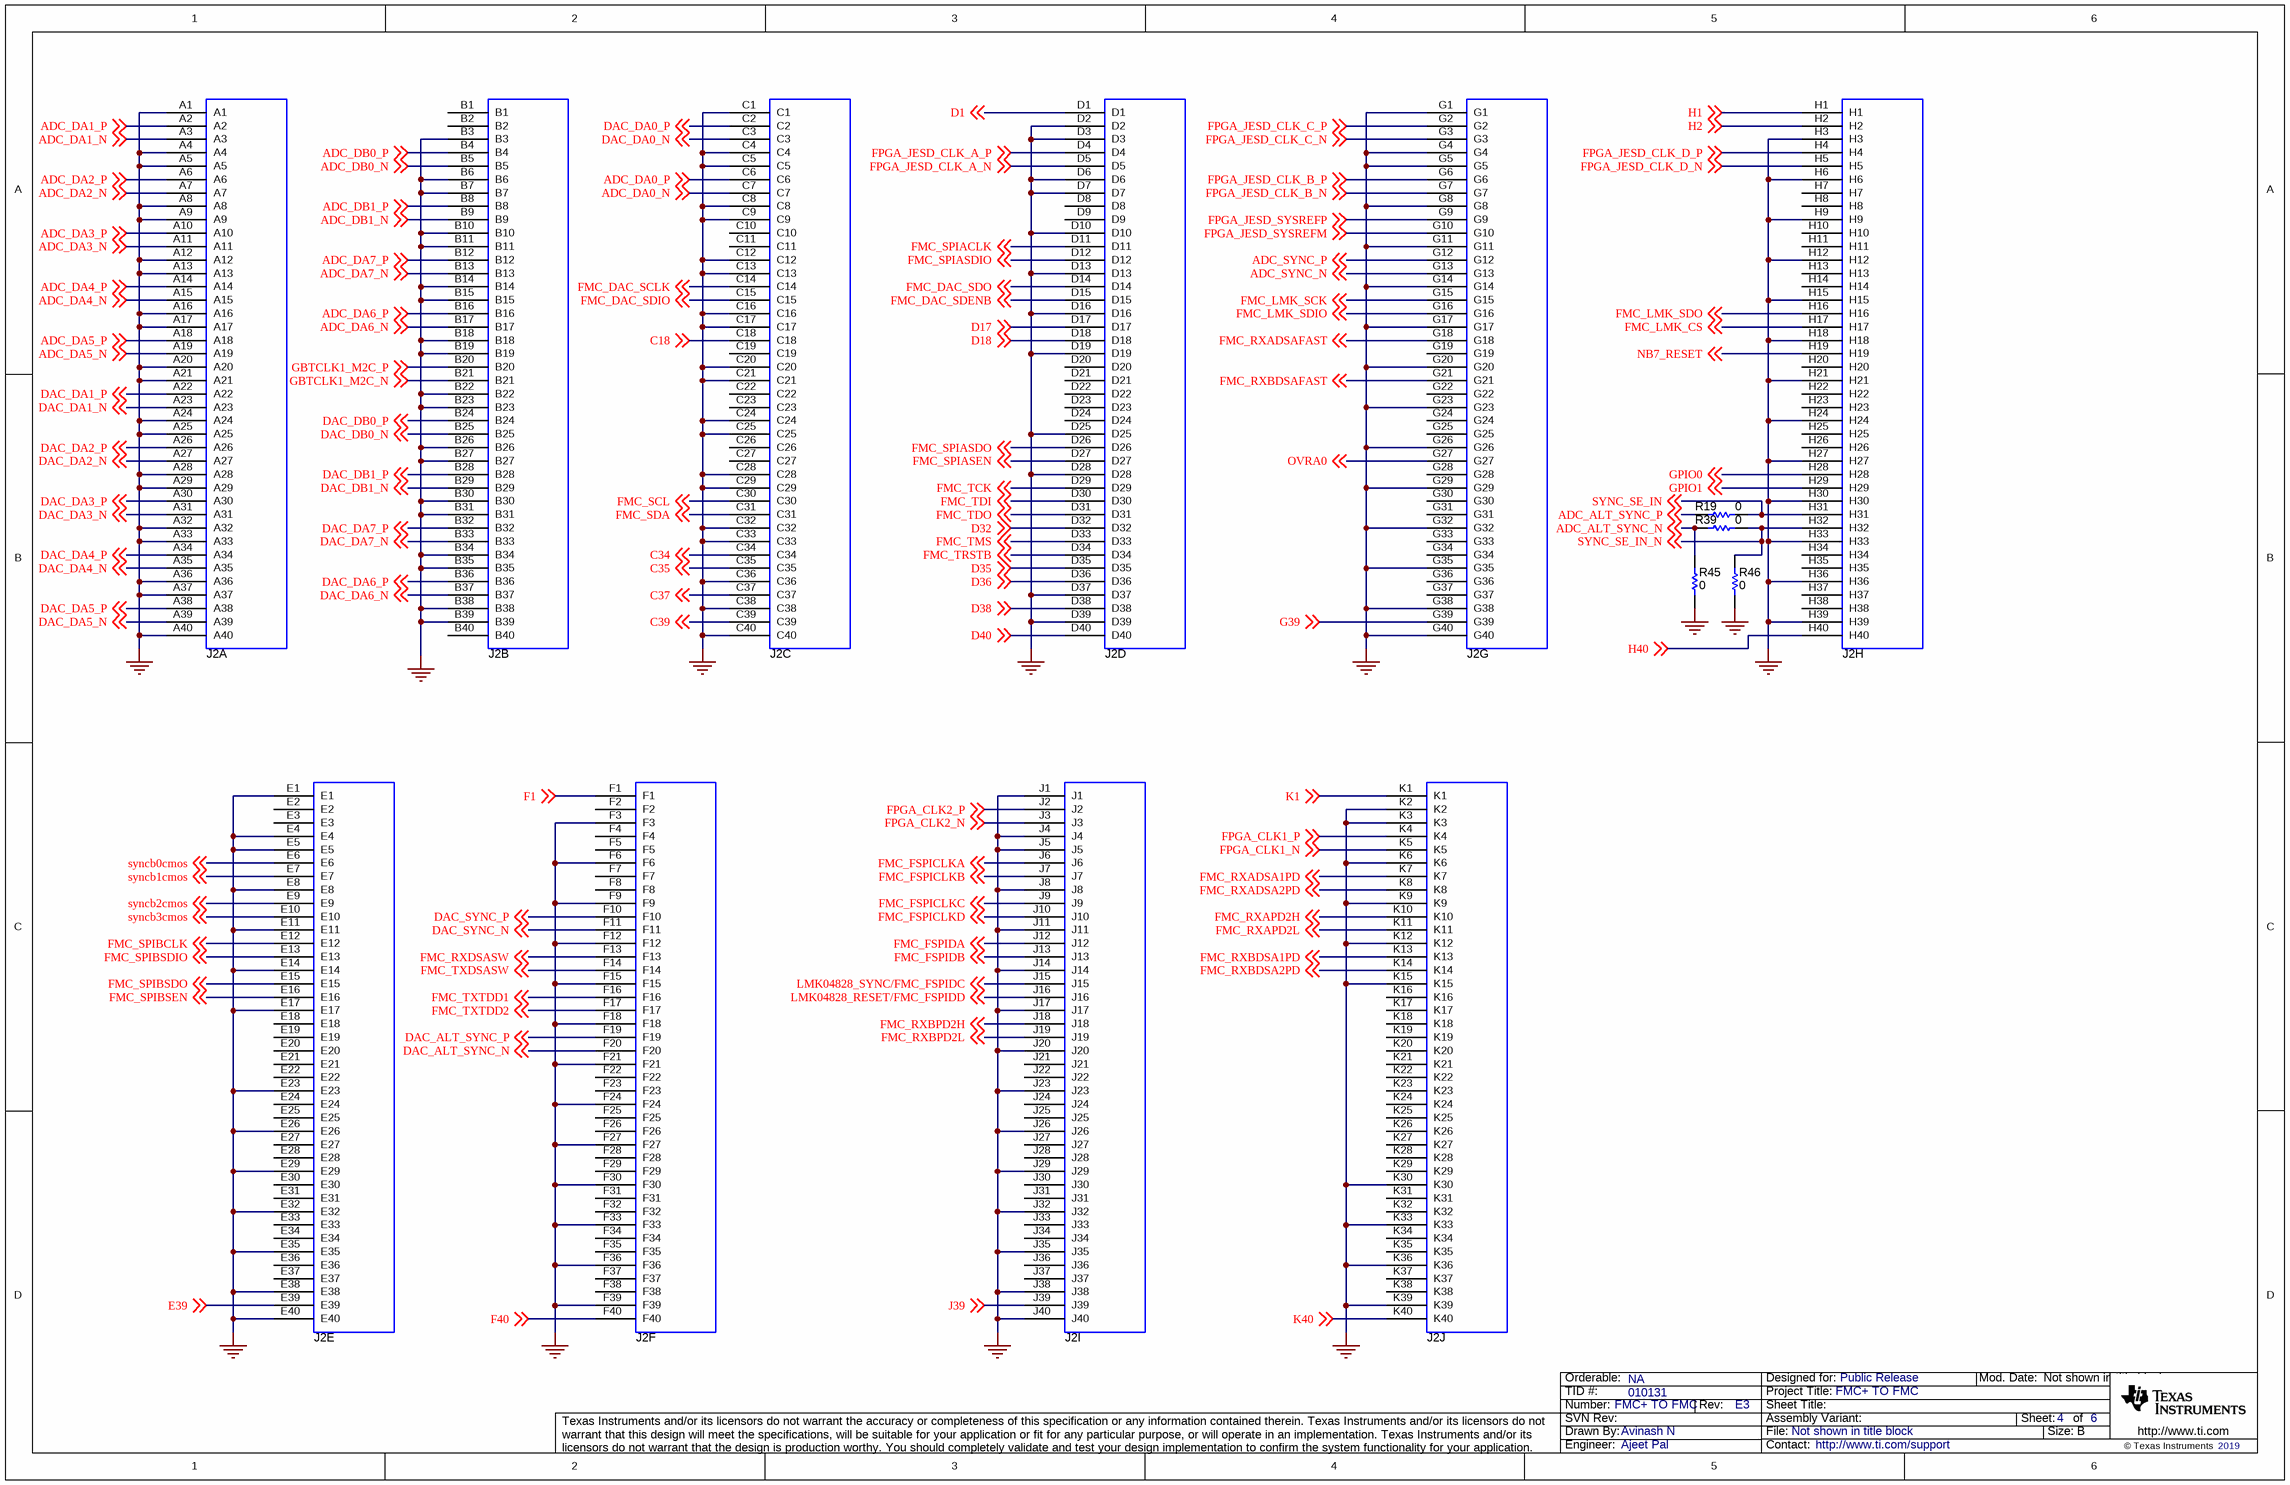
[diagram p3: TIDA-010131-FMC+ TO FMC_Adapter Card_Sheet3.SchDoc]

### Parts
J2  ASP-134488-01  [Samtec_ASP-134488-01]  (value not drawn)  (parts A,B,C,D,E,F,G,H,I,J of 10)
R19  ValueDisplayed: 0  [0402]  (hidden comment: CRCW04020000Z0ED)
R39  ValueDisplayed: 0  [0402]  (hidden comment: CRCW04020000Z0ED)
R45  ValueDisplayed: 0  [0402]  (hidden comment: CRCW04020000Z0ED)
R46  ValueDisplayed: 0  [0402]  (hidden comment: CRCW04020000Z0ED)

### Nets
GND: J2.A1 J2.A4 J2.A5 J2.A8 J2.A9 J2.A12 J2.A13 J2.A16 J2.A17 J2.A20 J2.A21 J2.A24 J2.A25 J2.A28 J2.A29 J2.A32 J2.A33 J2.A36 J2.A37 J2.A40 J2.B3 J2.B6 J2.B7 J2.B10 J2.B11 J2.B14 J2.B15 J2.B18 J2.B19 J2.B22 J2.B23 J2.B26 J2.B27 J2.B30 J2.B31 J2.B34 J2.B35 J2.B38 J2.B39 J2.C1 J2.C4 J2.C5 J2.C8 J2.C9 J2.C12 J2.C13 J2.C16 J2.C17 J2.C20 J2.C21 J2.C24 J2.C25 J2.C28 J2.C29 J2.C32 J2.C33 J2.C36 J2.C38 J2.C40 J2.D2 J2.D3 J2.D6 J2.D7 J2.D10 J2.D13 J2.D16 J2.D19 J2.D25 J2.D28 J2.D37 J2.D39 J2.E1 J2.E4 J2.E5 J2.E8 J2.E11 J2.E14 J2.E17 J2.E23 J2.E26 J2.E29 J2.E32 J2.E35 J2.E38 J2.E40 J2.F3 J2.F6 J2.F9 J2.F12 J2.F15 J2.F18 J2.F21 J2.F24 J2.F27 J2.F30 J2.F33 J2.F36 J2.F39 J2.G1 J2.G4 J2.G5 J2.G8 J2.G11 J2.G14 J2.G17 J2.G20 J2.G23 J2.G26 J2.G29 J2.G32 J2.G35 J2.G38 J2.G40 J2.H3 J2.H6 J2.H9 J2.H12 J2.H15 J2.H18 J2.H21 J2.H24 J2.H27 J2.H30 J2.H33 J2.H36 J2.H39 J2.J1 J2.J4 J2.J5 J2.J8 J2.J11 J2.J14 J2.J17 J2.J20 J2.J23 J2.J26 J2.J29 J2.J32 J2.J35 J2.J38 J2.J40 J2.K2 J2.K3 J2.K6 J2.K9 J2.K12 J2.K15 J2.K30 J2.K33 J2.K36 J2.K39 R45.1 R46.1
ADC_ALT_SYNC_N: R39.1 R45.2 ; off-sheet ADC_ALT_SYNC_N
ADC_ALT_SYNC_P: R19.1 ; off-sheet ADC_ALT_SYNC_P
ADC_DA0_N: J2.C7 ; off-sheet ADC_DA0_N
ADC_DA0_P: J2.C6 ; off-sheet ADC_DA0_P
ADC_DA1_N: J2.A3 ; off-sheet ADC_DA1_N
ADC_DA1_P: J2.A2 ; off-sheet ADC_DA1_P
ADC_DA2_N: J2.A7 ; off-sheet ADC_DA2_N
ADC_DA2_P: J2.A6 ; off-sheet ADC_DA2_P
ADC_DA3_N: J2.A11 ; off-sheet ADC_DA3_N
ADC_DA3_P: J2.A10 ; off-sheet ADC_DA3_P
ADC_DA4_N: J2.A15 ; off-sheet ADC_DA4_N
ADC_DA4_P: J2.A14 ; off-sheet ADC_DA4_P
ADC_DA5_N: J2.A19 ; off-sheet ADC_DA5_N
ADC_DA5_P: J2.A18 ; off-sheet ADC_DA5_P
ADC_DA6_N: J2.B17 ; off-sheet ADC_DA6_N
ADC_DA6_P: J2.B16 ; off-sheet ADC_DA6_P
ADC_DA7_N: J2.B13 ; off-sheet ADC_DA7_N
ADC_DA7_P: J2.B12 ; off-sheet ADC_DA7_P
ADC_DB0_N: J2.B5 ; off-sheet ADC_DB0_N
ADC_DB0_P: J2.B4 ; off-sheet ADC_DB0_P
ADC_DB1_N: J2.B9 ; off-sheet ADC_DB1_N
ADC_DB1_P: J2.B8 ; off-sheet ADC_DB1_P
ADC_SYNC_N: J2.G13 ; off-sheet ADC_SYNC_N
ADC_SYNC_P: J2.G12 ; off-sheet ADC_SYNC_P
C18: J2.C18 ; off-sheet C18
C34: J2.C34 ; off-sheet C34
C35: J2.C35 ; off-sheet C35
C37: J2.C37 ; off-sheet C37
C39: J2.C39 ; off-sheet C39
D1: J2.D1 ; off-sheet D1
D17: J2.D17 ; off-sheet D17
D18: J2.D18 ; off-sheet D18
D32: J2.D32 ; off-sheet D32
D35: J2.D35 ; off-sheet D35
D36: J2.D36 ; off-sheet D36
D38: J2.D38 ; off-sheet D38
D40: J2.D40 ; off-sheet D40
DAC_ALT_SYNC_N: J2.F20 ; off-sheet DAC_ALT_SYNC_N
DAC_ALT_SYNC_P: J2.F19 ; off-sheet DAC_ALT_SYNC_P
DAC_DA0_N: J2.C3 ; off-sheet DAC_DA0_N
DAC_DA0_P: J2.C2 ; off-sheet DAC_DA0_P
DAC_DA1_N: J2.A23 ; off-sheet DAC_DA1_N
DAC_DA1_P: J2.A22 ; off-sheet DAC_DA1_P
DAC_DA2_N: J2.A27 ; off-sheet DAC_DA2_N
DAC_DA2_P: J2.A26 ; off-sheet DAC_DA2_P
DAC_DA3_N: J2.A31 ; off-sheet DAC_DA3_N
DAC_DA3_P: J2.A30 ; off-sheet DAC_DA3_P
DAC_DA4_N: J2.A35 ; off-sheet DAC_DA4_N
DAC_DA4_P: J2.A34 ; off-sheet DAC_DA4_P
DAC_DA5_N: J2.A39 ; off-sheet DAC_DA5_N
DAC_DA5_P: J2.A38 ; off-sheet DAC_DA5_P
DAC_DA6_N: J2.B37 ; off-sheet DAC_DA6_N
DAC_DA6_P: J2.B36 ; off-sheet DAC_DA6_P
DAC_DA7_N: J2.B33 ; off-sheet DAC_DA7_N
DAC_DA7_P: J2.B32 ; off-sheet DAC_DA7_P
DAC_DB0_N: J2.B25 ; off-sheet DAC_DB0_N
DAC_DB0_P: J2.B24 ; off-sheet DAC_DB0_P
DAC_DB1_N: J2.B29 ; off-sheet DAC_DB1_N
DAC_DB1_P: J2.B28 ; off-sheet DAC_DB1_P
DAC_SYNC_N: J2.F11 ; off-sheet DAC_SYNC_N
DAC_SYNC_P: J2.F10 ; off-sheet DAC_SYNC_P
E39: J2.E39 ; off-sheet E39
F1: J2.F1 ; off-sheet F1
F40: J2.F40 ; off-sheet F40
FMC_DAC_SCLK: J2.C14 ; off-sheet FMC_DAC_SCLK
FMC_DAC_SDENB: J2.D15 ; off-sheet FMC_DAC_SDENB
FMC_DAC_SDIO: J2.C15 ; off-sheet FMC_DAC_SDIO
FMC_DAC_SDO: J2.D14 ; off-sheet FMC_DAC_SDO
FMC_FSPICLKA: J2.J6 ; off-sheet FMC_FSPICLKA
FMC_FSPICLKB: J2.J7 ; off-sheet FMC_FSPICLKB
FMC_FSPICLKC: J2.J9 ; off-sheet FMC_FSPICLKC
FMC_FSPICLKD: J2.J10 ; off-sheet FMC_FSPICLKD
FMC_FSPIDA: J2.J12 ; off-sheet FMC_FSPIDA
FMC_FSPIDB: J2.J13 ; off-sheet FMC_FSPIDB
FMC_LMK_CS: J2.H17 ; off-sheet FMC_LMK_CS
FMC_LMK_SCK: J2.G15 ; off-sheet FMC_LMK_SCK
FMC_LMK_SDIO: J2.G16 ; off-sheet FMC_LMK_SDIO
FMC_LMK_SDO: J2.H16 ; off-sheet FMC_LMK_SDO
FMC_RXADSA1PD: J2.K7 ; off-sheet FMC_RXADSA1PD
FMC_RXADSA2PD: J2.K8 ; off-sheet FMC_RXADSA2PD
FMC_RXADSAFAST: J2.G18 ; off-sheet FMC_RXADSAFAST
FMC_RXAPD2H: J2.K10 ; off-sheet FMC_RXAPD2H
FMC_RXAPD2L: J2.K11 ; off-sheet FMC_RXAPD2L
FMC_RXBDSA1PD: J2.K13 ; off-sheet FMC_RXBDSA1PD
FMC_RXBDSA2PD: J2.K14 ; off-sheet FMC_RXBDSA2PD
FMC_RXBDSAFAST: J2.G21 ; off-sheet FMC_RXBDSAFAST
FMC_RXBPD2H: J2.J18 ; off-sheet FMC_RXBPD2H
FMC_RXBPD2L: J2.J19 ; off-sheet FMC_RXBPD2L
FMC_RXDSASW: J2.F13 ; off-sheet FMC_RXDSASW
FMC_SCL: J2.C30 ; off-sheet FMC_SCL
FMC_SDA: J2.C31 ; off-sheet FMC_SDA
FMC_SPIACLK: J2.D11 ; off-sheet FMC_SPIACLK
FMC_SPIASDIO: J2.D12 ; off-sheet FMC_SPIASDIO
FMC_SPIASDO: J2.D26 ; off-sheet FMC_SPIASDO
FMC_SPIASEN: J2.D27 ; off-sheet FMC_SPIASEN
FMC_SPIBCLK: J2.E12 ; off-sheet FMC_SPIBCLK
FMC_SPIBSDIO: J2.E13 ; off-sheet FMC_SPIBSDIO
FMC_SPIBSDO: J2.E15 ; off-sheet FMC_SPIBSDO
FMC_SPIBSEN: J2.E16 ; off-sheet FMC_SPIBSEN
FMC_TCK: J2.D29 ; off-sheet FMC_TCK
FMC_TDI: J2.D30 ; off-sheet FMC_TDI
FMC_TDO: J2.D31 ; off-sheet FMC_TDO
FMC_TMS: J2.D33 ; off-sheet FMC_TMS
FMC_TRSTB: J2.D34 ; off-sheet FMC_TRSTB
FMC_TXDSASW: J2.F14 ; off-sheet FMC_TXDSASW
FMC_TXTDD1: J2.F16 ; off-sheet FMC_TXTDD1
FMC_TXTDD2: J2.F17 ; off-sheet FMC_TXTDD2
FPGA_CLK1_N: J2.K5 ; off-sheet FPGA_CLK1_N
FPGA_CLK1_P: J2.K4 ; off-sheet FPGA_CLK1_P
FPGA_CLK2_N: J2.J3 ; off-sheet FPGA_CLK2_N
FPGA_CLK2_P: J2.J2 ; off-sheet FPGA_CLK2_P
FPGA_JESD_CLK_A_N: J2.D5 ; off-sheet FPGA_JESD_CLK_A_N
FPGA_JESD_CLK_A_P: J2.D4 ; off-sheet FPGA_JESD_CLK_A_P
FPGA_JESD_CLK_B_N: J2.G7 ; off-sheet FPGA_JESD_CLK_B_N
FPGA_JESD_CLK_B_P: J2.G6 ; off-sheet FPGA_JESD_CLK_B_P
FPGA_JESD_CLK_C_N: J2.G3 ; off-sheet FPGA_JESD_CLK_C_N
FPGA_JESD_CLK_C_P: J2.G2 ; off-sheet FPGA_JESD_CLK_C_P
FPGA_JESD_CLK_D_N: J2.H5 ; off-sheet FPGA_JESD_CLK_D_N
FPGA_JESD_CLK_D_P: J2.H4 ; off-sheet FPGA_JESD_CLK_D_P
FPGA_JESD_SYSREFM: J2.G10 ; off-sheet FPGA_JESD_SYSREFM
FPGA_JESD_SYSREFP: J2.G9 ; off-sheet FPGA_JESD_SYSREFP
G39: J2.G39 ; off-sheet G39
GBTCLK1_M2C_N: J2.B21 ; off-sheet GBTCLK1_M2C_N
GBTCLK1_M2C_P: J2.B20 ; off-sheet GBTCLK1_M2C_P
GPIO0: J2.H28 ; off-sheet GPIO0
GPIO1: J2.H29 ; off-sheet GPIO1
H1: J2.H1 ; off-sheet H1
H2: J2.H2 ; off-sheet H2
H40: J2.H40 ; off-sheet H40
J39: J2.J39 ; off-sheet J39
K1: J2.K1 ; off-sheet K1
K40: J2.K40 ; off-sheet K40
LMK04828_RESET/FMC_FSPIDD: J2.J16 ; off-sheet LMK04828_RESET/FMC_FSPIDD
LMK04828_SYNC/FMC_FSPIDC: J2.J15 ; off-sheet LMK04828_SYNC/FMC_FSPIDC
NB7_RESET: J2.H19 ; off-sheet NB7_RESET
OVRA0: J2.G27 ; off-sheet OVRA0
SYNC_SE_IN: J2.H31 R19.2 ; off-sheet SYNC_SE_IN
SYNC_SE_IN_N: J2.H32 R39.2 R46.2 ; off-sheet SYNC_SE_IN_N
syncb0cmos: J2.E6 ; off-sheet syncb0cmos
syncb1cmos: J2.E7 ; off-sheet syncb1cmos
syncb2cmos: J2.E9 ; off-sheet syncb2cmos
syncb3cmos: J2.E10 ; off-sheet syncb3cmos

Not connected (* = marked no-connect by the designer): J2 B1 B2 B40 C10 C11 C19 C22 C23 C26 C27 D8 D9 D20 D21 D22 D23 D24 E2 E3 E18 E19 E20 E21 E22 E24 E25 E27 E28 E30 E31 E33 E34 E36 E37 F2 F4 F5 F7 F8 F22 F23 F25 F26 F28 F29 F31 F32 F34 F35 F37 F38 G19 G22 G24 G25 G28 G30 G31 G33 G34 G36 G37 H7 H8 H10 H11 H13 H14 H20 H22 H23 H25 H26 H34 H35 H37 H38 J21 J22 J24 J25 J27 J28 J30 J31 J33 J34 J36 J37 K16 K17 K18 K19 K20 K21 K22 K23 K24 K25 K26 K27 K28 K29 K31 K32 K34 K35 K37 K38

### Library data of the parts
J2 = ASP-134488-01: Connector, 1.27mm, 40x10, Black, SMT; Manufacturer: Samtec; SymbolCreator: Altium; CompType: Terminal Block; Pitch_mm: 1.27; Gender: Male; Row_Count: 10; Cert_UL: Y
R19 R39 R45 R46 = CRCW04020000Z0ED: as R8 on sheet TIDA-010131-FMC+ TO FMC_Adapter Card_Sheet1

## Sheet TIDA-010131-FMC+ TO FMC_Adapter Card_Sheet4.SchDoc
size 431 x 279 mm; Date: Not shown in title block; ApprovedBy: Not shown in title block; CheckedBy: Not shown in title block; Author: Not shown in title block; CompanyName: Not shown in title block; DrawnBy: Avinash N; Engineer: Not shown in title block; Organization: Not shown in title block; Address1: Not shown in title block; Address2: Not shown in title block; Address3: Not shown in title block; Address4: Not shown in title block; DocumentNumber: 5; Revision: Use project parameter SCH_Rev; SheetNumber: 5; SheetTotal: 6; PageSetup: Record=PageOptions¦CenterHorizontal=True¦CenterVertical=True¦PrintScale=0.64¦XCorrection=1.00¦YCorrection=1.00¦PrintKind=0¦BorderSize=5000000¦LeftOffset=0¦BottomOffset=0¦Orientation=2¦PaperLength=1000¦PaperWidth=1000¦Scale=100¦PaperSource=15¦PrintQuality=600¦MediaType=1¦DitherType=10¦PrintScaleMode=1¦PaperKind=Letter
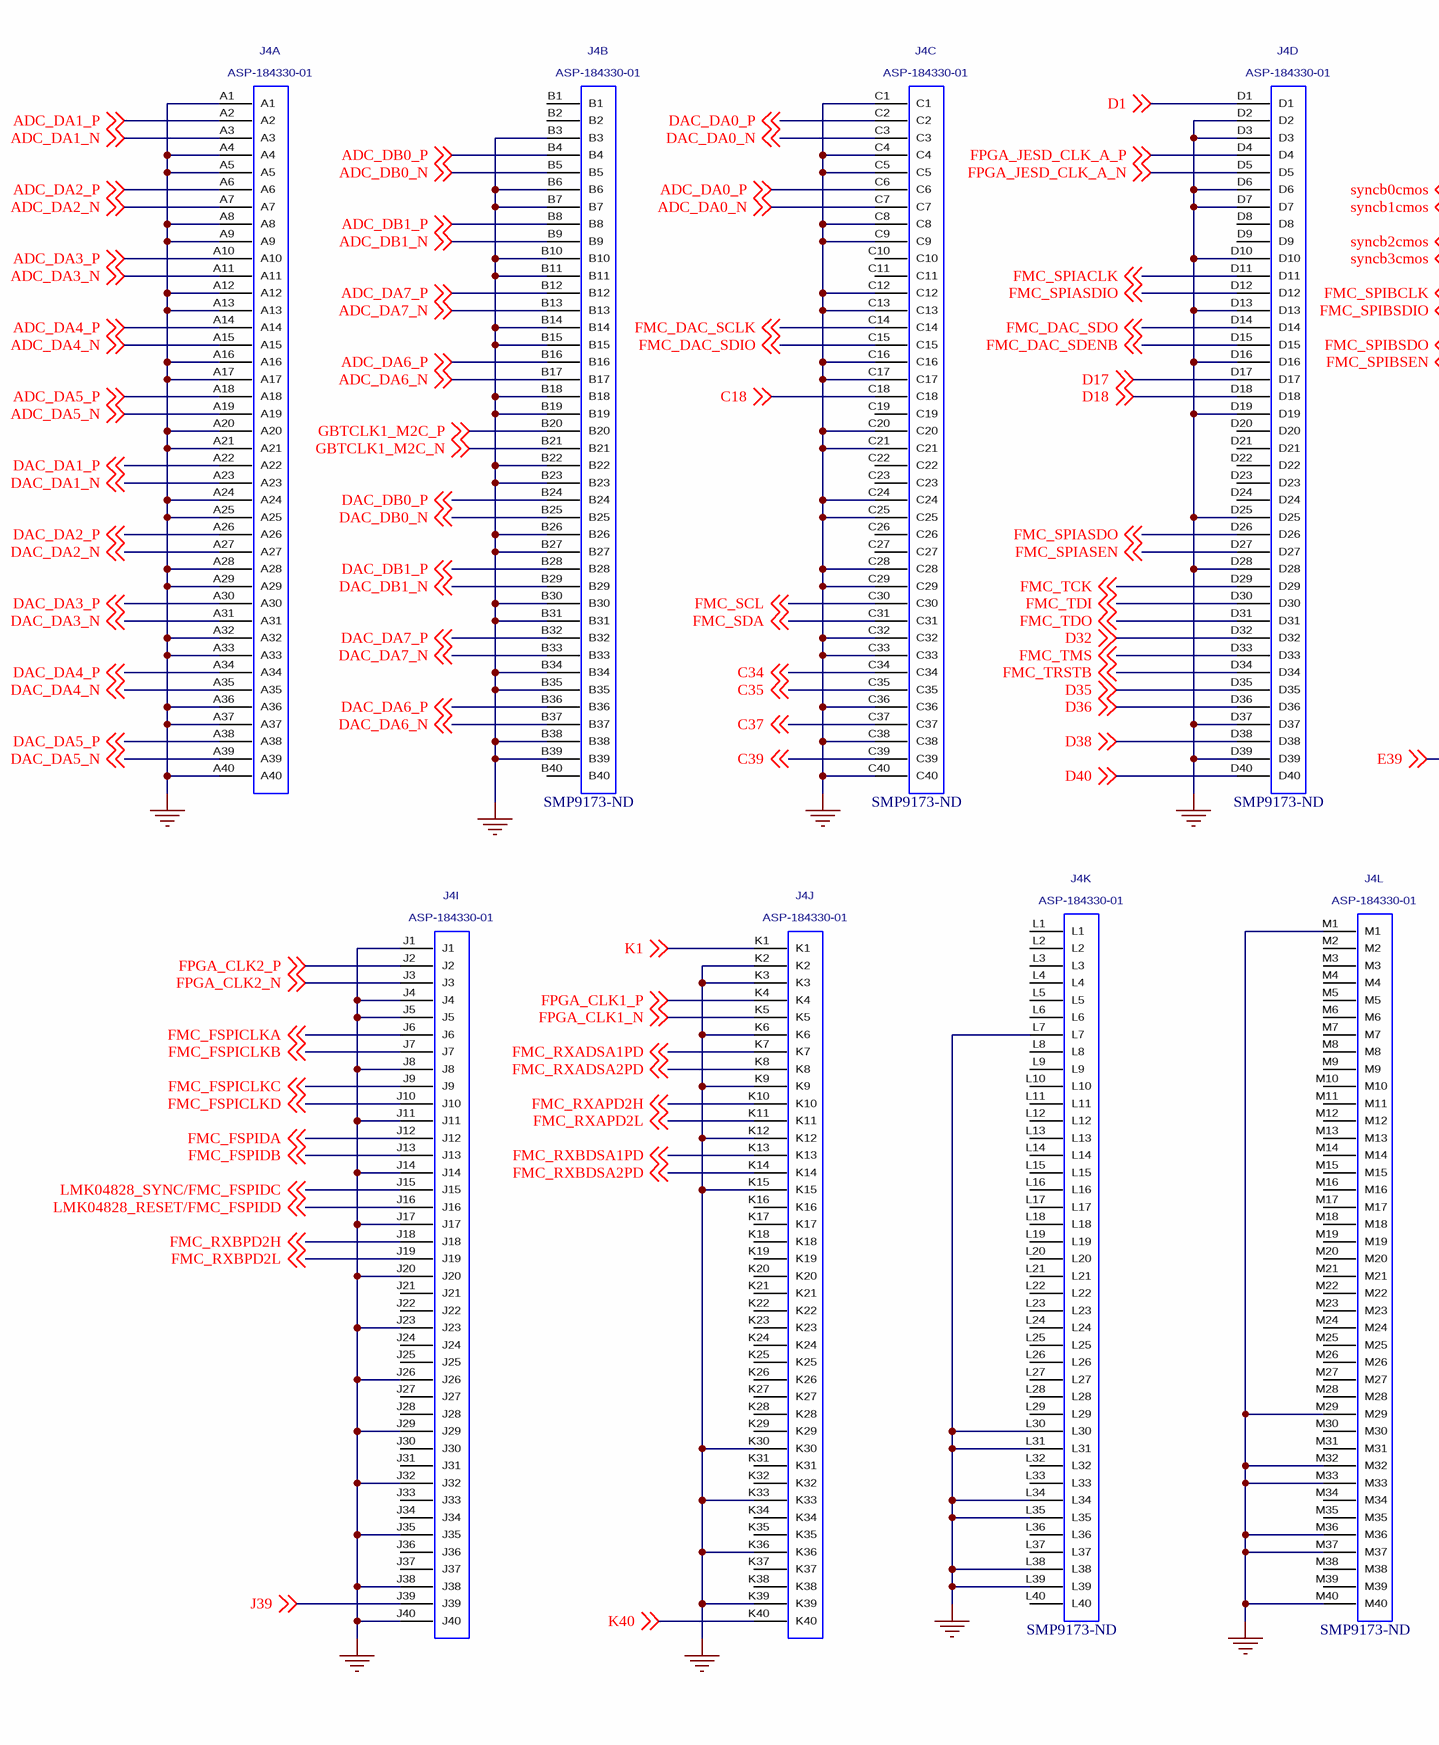
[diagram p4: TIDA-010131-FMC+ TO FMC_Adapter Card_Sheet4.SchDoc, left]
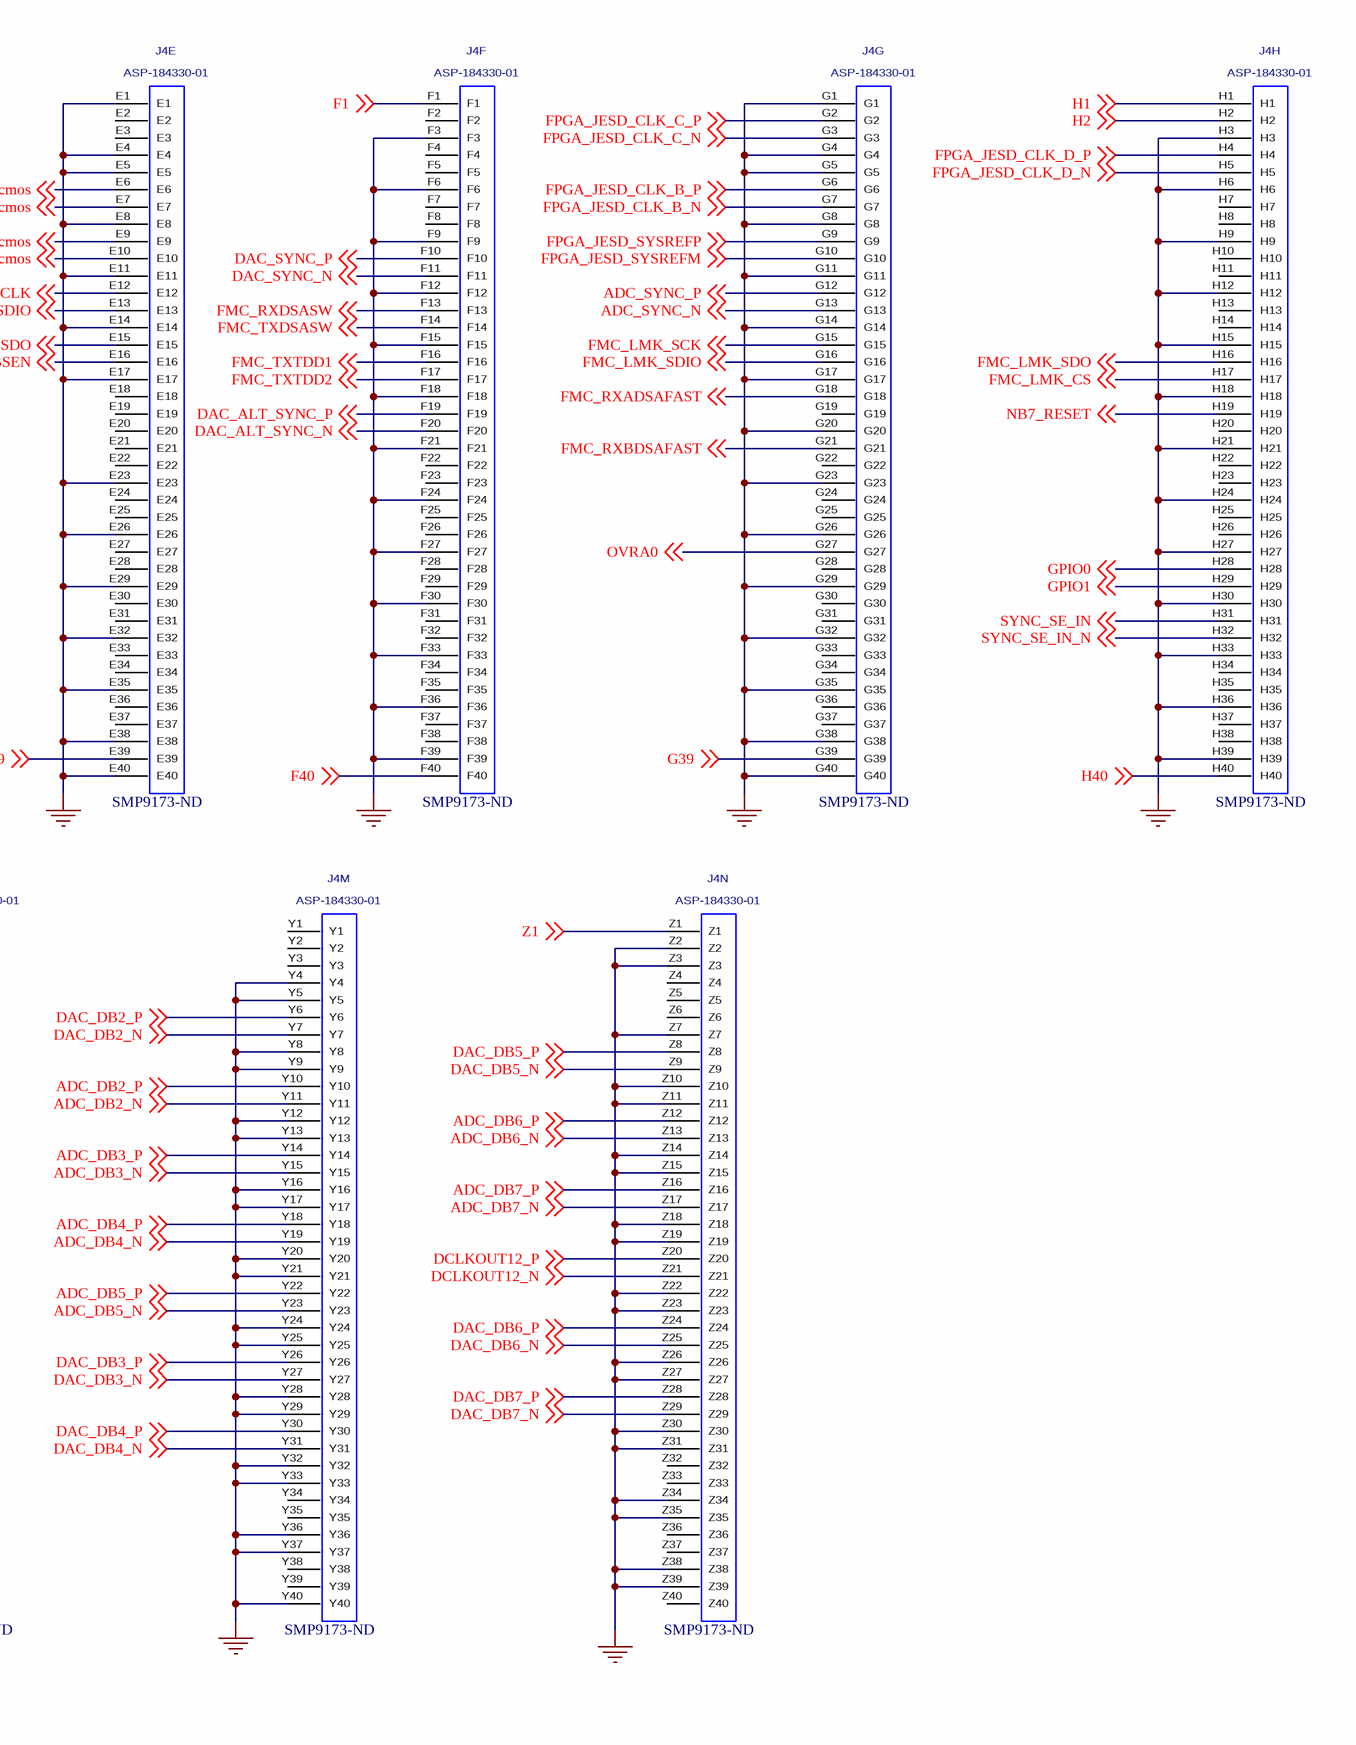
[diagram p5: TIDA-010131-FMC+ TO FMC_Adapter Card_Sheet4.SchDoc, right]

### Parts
J4  ASP-184330-01  [ASP-184330-01]  (parts A,B,C,D,E,F,G,H,I,J,K,L,M,N of 14)

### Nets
GND: J4.A1 J4.A4 J4.A5 J4.A8 J4.A9 J4.A12 J4.A13 J4.A16 J4.A17 J4.A20 J4.A21 J4.A24 J4.A25 J4.A28 J4.A29 J4.A32 J4.A33 J4.A36 J4.A37 J4.A40 J4.B3 J4.B6 J4.B7 J4.B10 J4.B11 J4.B14 J4.B15 J4.B18 J4.B19 J4.B22 J4.B23 J4.B26 J4.B27 J4.B30 J4.B31 J4.B34 J4.B35 J4.B38 J4.B39 J4.C1 J4.C4 J4.C5 J4.C8 J4.C9 J4.C12 J4.C13 J4.C16 J4.C17 J4.C20 J4.C21 J4.C24 J4.C25 J4.C28 J4.C29 J4.C32 J4.C33 J4.C36 J4.C38 J4.C40 J4.D2 J4.D3 J4.D6 J4.D7 J4.D10 J4.D13 J4.D16 J4.D19 J4.D25 J4.D28 J4.D37 J4.D39 J4.E1 J4.E4 J4.E5 J4.E8 J4.E11 J4.E14 J4.E17 J4.E23 J4.E26 J4.E29 J4.E32 J4.E35 J4.E38 J4.E40 J4.F3 J4.F6 J4.F9 J4.F12 J4.F15 J4.F18 J4.F21 J4.F24 J4.F27 J4.F30 J4.F33 J4.F36 J4.F39 J4.G1 J4.G4 J4.G5 J4.G8 J4.G11 J4.G14 J4.G17 J4.G20 J4.G23 J4.G26 J4.G29 J4.G32 J4.G35 J4.G38 J4.G40 J4.H3 J4.H6 J4.H9 J4.H12 J4.H15 J4.H18 J4.H21 J4.H24 J4.H27 J4.H30 J4.H33 J4.H36 J4.H39 J4.J1 J4.J4 J4.J5 J4.J8 J4.J11 J4.J14 J4.J17 J4.J20 J4.J23 J4.J26 J4.J29 J4.J32 J4.J35 J4.J38 J4.J40 J4.K2 J4.K3 J4.K6 J4.K9 J4.K12 J4.K15 J4.K30 J4.K33 J4.K36 J4.K39 J4.L7 J4.L30 J4.L31 J4.L34 J4.L35 J4.L38 J4.L39 J4.M1 J4.M29 J4.M32 J4.M33 J4.M36 J4.M37 J4.M40 J4.Y4 J4.Y5 J4.Y8 J4.Y9 J4.Y12 J4.Y13 J4.Y16 J4.Y17 J4.Y20 J4.Y21 J4.Y24 J4.Y25 J4.Y28 J4.Y29 J4.Y32 J4.Y33 J4.Y36 J4.Y37 J4.Y40 J4.Z2 J4.Z3 J4.Z7 J4.Z10 J4.Z11 J4.Z14 J4.Z15 J4.Z18 J4.Z19 J4.Z22 J4.Z23 J4.Z26 J4.Z27 J4.Z30 J4.Z31 J4.Z34 J4.Z35 J4.Z38 J4.Z39
ADC_DA0_N: J4.C7 ; off-sheet ADC_DA0_N
ADC_DA0_P: J4.C6 ; off-sheet ADC_DA0_P
ADC_DA1_N: J4.A3 ; off-sheet ADC_DA1_N
ADC_DA1_P: J4.A2 ; off-sheet ADC_DA1_P
ADC_DA2_N: J4.A7 ; off-sheet ADC_DA2_N
ADC_DA2_P: J4.A6 ; off-sheet ADC_DA2_P
ADC_DA3_N: J4.A11 ; off-sheet ADC_DA3_N
ADC_DA3_P: J4.A10 ; off-sheet ADC_DA3_P
ADC_DA4_N: J4.A15 ; off-sheet ADC_DA4_N
ADC_DA4_P: J4.A14 ; off-sheet ADC_DA4_P
ADC_DA5_N: J4.A19 ; off-sheet ADC_DA5_N
ADC_DA5_P: J4.A18 ; off-sheet ADC_DA5_P
ADC_DA6_N: J4.B17 ; off-sheet ADC_DA6_N
ADC_DA6_P: J4.B16 ; off-sheet ADC_DA6_P
ADC_DA7_N: J4.B13 ; off-sheet ADC_DA7_N
ADC_DA7_P: J4.B12 ; off-sheet ADC_DA7_P
ADC_DB0_N: J4.B5 ; off-sheet ADC_DB0_N
ADC_DB0_P: J4.B4 ; off-sheet ADC_DB0_P
ADC_DB1_N: J4.B9 ; off-sheet ADC_DB1_N
ADC_DB1_P: J4.B8 ; off-sheet ADC_DB1_P
ADC_DB2_N: J4.Y11 ; off-sheet ADC_DB2_N
ADC_DB2_P: J4.Y10 ; off-sheet ADC_DB2_P
ADC_DB3_N: J4.Y15 ; off-sheet ADC_DB3_N
ADC_DB3_P: J4.Y14 ; off-sheet ADC_DB3_P
ADC_DB4_N: J4.Y19 ; off-sheet ADC_DB4_N
ADC_DB4_P: J4.Y18 ; off-sheet ADC_DB4_P
ADC_DB5_N: J4.Y23 ; off-sheet ADC_DB5_N
ADC_DB5_P: J4.Y22 ; off-sheet ADC_DB5_P
ADC_DB6_N: J4.Z13 ; off-sheet ADC_DB6_N
ADC_DB6_P: J4.Z12 ; off-sheet ADC_DB6_P
ADC_DB7_N: J4.Z17 ; off-sheet ADC_DB7_N
ADC_DB7_P: J4.Z16 ; off-sheet ADC_DB7_P
ADC_SYNC_N: J4.G13 ; off-sheet ADC_SYNC_N
ADC_SYNC_P: J4.G12 ; off-sheet ADC_SYNC_P
C18: J4.C18 ; off-sheet C18
C34: J4.C34 ; off-sheet C34
C35: J4.C35 ; off-sheet C35
C37: J4.C37 ; off-sheet C37
C39: J4.C39 ; off-sheet C39
D1: J4.D1 ; off-sheet D1
D17: J4.D17 ; off-sheet D17
D18: J4.D18 ; off-sheet D18
D32: J4.D32 ; off-sheet D32
D35: J4.D35 ; off-sheet D35
D36: J4.D36 ; off-sheet D36
D38: J4.D38 ; off-sheet D38
D40: J4.D40 ; off-sheet D40
DAC_ALT_SYNC_N: J4.F20 ; off-sheet DAC_ALT_SYNC_N
DAC_ALT_SYNC_P: J4.F19 ; off-sheet DAC_ALT_SYNC_P
DAC_DA0_N: J4.C3 ; off-sheet DAC_DA0_N
DAC_DA0_P: J4.C2 ; off-sheet DAC_DA0_P
DAC_DA1_N: J4.A23 ; off-sheet DAC_DA1_N
DAC_DA1_P: J4.A22 ; off-sheet DAC_DA1_P
DAC_DA2_N: J4.A27 ; off-sheet DAC_DA2_N
DAC_DA2_P: J4.A26 ; off-sheet DAC_DA2_P
DAC_DA3_N: J4.A31 ; off-sheet DAC_DA3_N
DAC_DA3_P: J4.A30 ; off-sheet DAC_DA3_P
DAC_DA4_N: J4.A35 ; off-sheet DAC_DA4_N
DAC_DA4_P: J4.A34 ; off-sheet DAC_DA4_P
DAC_DA5_N: J4.A39 ; off-sheet DAC_DA5_N
DAC_DA5_P: J4.A38 ; off-sheet DAC_DA5_P
DAC_DA6_N: J4.B37 ; off-sheet DAC_DA6_N
DAC_DA6_P: J4.B36 ; off-sheet DAC_DA6_P
DAC_DA7_N: J4.B33 ; off-sheet DAC_DA7_N
DAC_DA7_P: J4.B32 ; off-sheet DAC_DA7_P
DAC_DB0_N: J4.B25 ; off-sheet DAC_DB0_N
DAC_DB0_P: J4.B24 ; off-sheet DAC_DB0_P
DAC_DB1_N: J4.B29 ; off-sheet DAC_DB1_N
DAC_DB1_P: J4.B28 ; off-sheet DAC_DB1_P
DAC_DB2_N: J4.Y7 ; off-sheet DAC_DB2_N
DAC_DB2_P: J4.Y6 ; off-sheet DAC_DB2_P
DAC_DB3_N: J4.Y27 ; off-sheet DAC_DB3_N
DAC_DB3_P: J4.Y26 ; off-sheet DAC_DB3_P
DAC_DB4_N: J4.Y31 ; off-sheet DAC_DB4_N
DAC_DB4_P: J4.Y30 ; off-sheet DAC_DB4_P
DAC_DB5_N: J4.Z9 ; off-sheet DAC_DB5_N
DAC_DB5_P: J4.Z8 ; off-sheet DAC_DB5_P
DAC_DB6_N: J4.Z25 ; off-sheet DAC_DB6_N
DAC_DB6_P: J4.Z24 ; off-sheet DAC_DB6_P
DAC_DB7_N: J4.Z29 ; off-sheet DAC_DB7_N
DAC_DB7_P: J4.Z28 ; off-sheet DAC_DB7_P
DAC_SYNC_N: J4.F11 ; off-sheet DAC_SYNC_N
DAC_SYNC_P: J4.F10 ; off-sheet DAC_SYNC_P
DCLKOUT12_N: J4.Z21 ; off-sheet DCLKOUT12_N
DCLKOUT12_P: J4.Z20 ; off-sheet DCLKOUT12_P
E39: J4.E39 ; off-sheet E39
F1: J4.F1 ; off-sheet F1
F40: J4.F40 ; off-sheet F40
FMC_DAC_SCLK: J4.C14 ; off-sheet FMC_DAC_SCLK
FMC_DAC_SDENB: J4.D15 ; off-sheet FMC_DAC_SDENB
FMC_DAC_SDIO: J4.C15 ; off-sheet FMC_DAC_SDIO
FMC_DAC_SDO: J4.D14 ; off-sheet FMC_DAC_SDO
FMC_FSPICLKA: J4.J6 ; off-sheet FMC_FSPICLKA
FMC_FSPICLKB: J4.J7 ; off-sheet FMC_FSPICLKB
FMC_FSPICLKC: J4.J9 ; off-sheet FMC_FSPICLKC
FMC_FSPICLKD: J4.J10 ; off-sheet FMC_FSPICLKD
FMC_FSPIDA: J4.J12 ; off-sheet FMC_FSPIDA
FMC_FSPIDB: J4.J13 ; off-sheet FMC_FSPIDB
FMC_LMK_CS: J4.H17 ; off-sheet FMC_LMK_CS
FMC_LMK_SCK: J4.G15 ; off-sheet FMC_LMK_SCK
FMC_LMK_SDIO: J4.G16 ; off-sheet FMC_LMK_SDIO
FMC_LMK_SDO: J4.H16 ; off-sheet FMC_LMK_SDO
FMC_RXADSA1PD: J4.K7 ; off-sheet FMC_RXADSA1PD
FMC_RXADSA2PD: J4.K8 ; off-sheet FMC_RXADSA2PD
FMC_RXADSAFAST: J4.G18 ; off-sheet FMC_RXADSAFAST
FMC_RXAPD2H: J4.K10 ; off-sheet FMC_RXAPD2H
FMC_RXAPD2L: J4.K11 ; off-sheet FMC_RXAPD2L
FMC_RXBDSA1PD: J4.K13 ; off-sheet FMC_RXBDSA1PD
FMC_RXBDSA2PD: J4.K14 ; off-sheet FMC_RXBDSA2PD
FMC_RXBDSAFAST: J4.G21 ; off-sheet FMC_RXBDSAFAST
FMC_RXBPD2H: J4.J18 ; off-sheet FMC_RXBPD2H
FMC_RXBPD2L: J4.J19 ; off-sheet FMC_RXBPD2L
FMC_RXDSASW: J4.F13 ; off-sheet FMC_RXDSASW
FMC_SCL: J4.C30 ; off-sheet FMC_SCL
FMC_SDA: J4.C31 ; off-sheet FMC_SDA
FMC_SPIACLK: J4.D11 ; off-sheet FMC_SPIACLK
FMC_SPIASDIO: J4.D12 ; off-sheet FMC_SPIASDIO
FMC_SPIASDO: J4.D26 ; off-sheet FMC_SPIASDO
FMC_SPIASEN: J4.D27 ; off-sheet FMC_SPIASEN
FMC_SPIBCLK: J4.E12 ; off-sheet FMC_SPIBCLK
FMC_SPIBSDIO: J4.E13 ; off-sheet FMC_SPIBSDIO
FMC_SPIBSDO: J4.E15 ; off-sheet FMC_SPIBSDO
FMC_SPIBSEN: J4.E16 ; off-sheet FMC_SPIBSEN
FMC_TCK: J4.D29 ; off-sheet FMC_TCK
FMC_TDI: J4.D30 ; off-sheet FMC_TDI
FMC_TDO: J4.D31 ; off-sheet FMC_TDO
FMC_TMS: J4.D33 ; off-sheet FMC_TMS
FMC_TRSTB: J4.D34 ; off-sheet FMC_TRSTB
FMC_TXDSASW: J4.F14 ; off-sheet FMC_TXDSASW
FMC_TXTDD1: J4.F16 ; off-sheet FMC_TXTDD1
FMC_TXTDD2: J4.F17 ; off-sheet FMC_TXTDD2
FPGA_CLK1_N: J4.K5 ; off-sheet FPGA_CLK1_N
FPGA_CLK1_P: J4.K4 ; off-sheet FPGA_CLK1_P
FPGA_CLK2_N: J4.J3 ; off-sheet FPGA_CLK2_N
FPGA_CLK2_P: J4.J2 ; off-sheet FPGA_CLK2_P
FPGA_JESD_CLK_A_N: J4.D5 ; off-sheet FPGA_JESD_CLK_A_N
FPGA_JESD_CLK_A_P: J4.D4 ; off-sheet FPGA_JESD_CLK_A_P
FPGA_JESD_CLK_B_N: J4.G7 ; off-sheet FPGA_JESD_CLK_B_N
FPGA_JESD_CLK_B_P: J4.G6 ; off-sheet FPGA_JESD_CLK_B_P
FPGA_JESD_CLK_C_N: J4.G3 ; off-sheet FPGA_JESD_CLK_C_N
FPGA_JESD_CLK_C_P: J4.G2 ; off-sheet FPGA_JESD_CLK_C_P
FPGA_JESD_CLK_D_N: J4.H5 ; off-sheet FPGA_JESD_CLK_D_N
FPGA_JESD_CLK_D_P: J4.H4 ; off-sheet FPGA_JESD_CLK_D_P
FPGA_JESD_SYSREFM: J4.G10 ; off-sheet FPGA_JESD_SYSREFM
FPGA_JESD_SYSREFP: J4.G9 ; off-sheet FPGA_JESD_SYSREFP
G39: J4.G39 ; off-sheet G39
GBTCLK1_M2C_N: J4.B21 ; off-sheet GBTCLK1_M2C_N
GBTCLK1_M2C_P: J4.B20 ; off-sheet GBTCLK1_M2C_P
GPIO0: J4.H28 ; off-sheet GPIO0
GPIO1: J4.H29 ; off-sheet GPIO1
H1: J4.H1 ; off-sheet H1
H2: J4.H2 ; off-sheet H2
H40: J4.H40 ; off-sheet H40
J39: J4.J39 ; off-sheet J39
K1: J4.K1 ; off-sheet K1
K40: J4.K40 ; off-sheet K40
LMK04828_RESET/FMC_FSPIDD: J4.J16 ; off-sheet LMK04828_RESET/FMC_FSPIDD
LMK04828_SYNC/FMC_FSPIDC: J4.J15 ; off-sheet LMK04828_SYNC/FMC_FSPIDC
NB7_RESET: J4.H19 ; off-sheet NB7_RESET
OVRA0: J4.G27 ; off-sheet OVRA0
SYNC_SE_IN: J4.H31 ; off-sheet SYNC_SE_IN
SYNC_SE_IN_N: J4.H32 ; off-sheet SYNC_SE_IN_N
syncb0cmos: J4.E6 ; off-sheet syncb0cmos
syncb1cmos: J4.E7 ; off-sheet syncb1cmos
syncb2cmos: J4.E9 ; off-sheet syncb2cmos
syncb3cmos: J4.E10 ; off-sheet syncb3cmos
Z1: J4.Z1 ; off-sheet Z1

Not connected (* = marked no-connect by the designer): J4 B1 B2 B40 C10 C11 C19 C22 C23 C26 C27 D8 D9 D20 D21 D22 D23 D24 E2 E3 E18 E19 E20 E21 E22 E24 E25 E27 E28 E30 E31 E33 E34 E36 E37 F2 F4 F5 F7 F8 F22 F23 F25 F26 F28 F29 F31 F32 F34 F35 F37 F38 G19 G22 G24 G25 G28 G30 G31 G33 G34 G36 G37 H7 H8 H10 H11 H13 H14 H20 H22 H23 H25 H26 H34 H35 H37 H38 J21 J22 J24 J25 J27 J28 J30 J31 J33 J34 J36 J37 K16 K17 K18 K19 K20 K21 K22 K23 K24 K25 K26 K27 K28 K29 K31 K32 K34 K35 K37 K38 L1 L2 L3 L4 L5 L6 L8 L9 L10 L11 L12 L13 L14 L15 L16 L17 L18 L19 L20 L21 L22 L23 L24 L25 L26 L27 L28 L29 L32 L33 L36 L37 L40 M2 M3 M4 M5 M6 M7 M8 M9 M10 M11 M12 M13 M14 M15 M16 M17 M18 M19 M20 M21 M22 M23 M24 M25 M26 M27 M28 M30 M31 M34 M35 M38 M39 Y1 Y2 Y3 Y34 Y35 Y38 Y39 Z4 Z5 Z6 Z32 Z33 Z36 Z37 Z40

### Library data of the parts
J4 = ASP-184330-01: 14 ROW .050 PITCH TERMINAL ARRAY ASM.; MANUFACTURER: SAMTEC

## Sheet TIDA-010131-FMC+ TO FMC_Adapter Card_Hardware.SchDoc
size 431 x 279 mm; Date: Not shown in title block; ApprovedBy: Not shown in title block; CheckedBy: Not shown in title block; Author: Not shown in title block; CompanyName: Not shown in title block; Engineer: Not shown in title block; Organization: Not shown in title block; Address1: Not shown in title block; Address2: Not shown in title block; Address3: Not shown in title block; Address4: Not shown in title block; DocumentNumber: 6; Revision: Use project parameter SCH_Rev; SheetNumber: 6; SheetTotal: 6; PageSetup: Record=PageOptions¦CenterHorizontal=True¦CenterVertical=True¦PrintScale=1.00¦XCorrection=1.00¦YCorrection=1.00¦PrintKind=0¦BorderSize=5000000¦LeftOffset=0¦BottomOffset=0¦Orientation=2¦PaperLength=1000¦PaperWidth=1000¦Scale=100¦PaperSource=15¦PrintQuality=600¦MediaType=1¦DitherType=10¦PaperKind=Letter¦PrintScaleMode=1
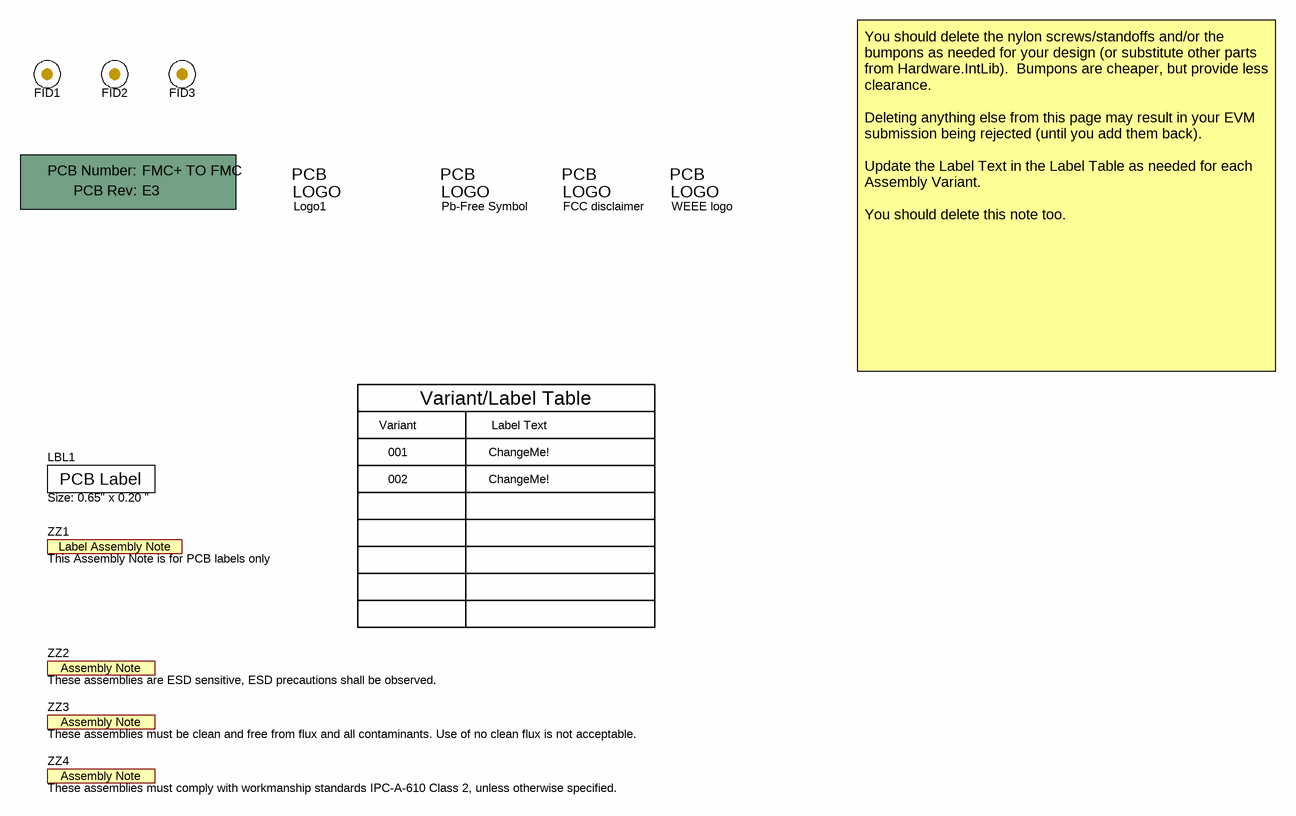
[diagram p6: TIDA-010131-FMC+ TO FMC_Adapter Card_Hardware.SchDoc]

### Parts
!PCB1  Printed Circuit Board  (value not drawn)  (mechanical)
FID1  Fiducial  [Fiducial10-20]  (value not drawn)
FID2  Fiducial  [Fiducial10-20]  (value not drawn)
FID3  Fiducial  [Fiducial10-20]  (value not drawn)
LBL1  Size: 0.65" x 0.20 "  [Label_650x200]
Logo1  ESD Susceptible  [ESD_Overlay_SMALL]  (value not drawn)  (no BOM)
Logo2  Pb-Free Symbol  [Pb-Free_Overlay_Small]  (no BOM)
Logo3  FCC disclaimer  [FCC_disclaimer]  (no BOM)
Logo4  WEEE logo  [WEEE_Minimum]  (no BOM)
ZZ1  This Assembly Note is for PCB labels only  [AssemblyNoteLabel]  (no BOM)
ZZ2  These assemblies are ESD sensitive, ESD precautions shall be observed.  [AssemblyNote]  (no BOM)
ZZ3  These assemblies must be clean and free from flux and all contaminants. Use of no clean flux is not acceptable.  [AssemblyNote]  (no BOM)
ZZ4  These assemblies must comply with workmanship standards IPC-A-610 Class 2, unless otherwise specified.  [AssemblyNote]  (no BOM)

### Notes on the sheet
- Variant
- Variant/Label Table
- Label Text
- You should delete the nylon screws/standoffs and/or the bumpons as needed for your design (or substitute other parts from Hardware.IntLib).  Bumpons are cheaper, but provide less clearance.
  Deleting anything else from this page may result in your EVM submission being rejected (until you add them back).
  Update the Label Text in the Label Table as needed for each Assembly Variant.
  You should delete this note too.
- 001
- 002
- ChangeMe!

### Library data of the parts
!PCB1 = PCB: Manufacturer: Any; PartNumber: FMC+ TO FMC; SymbolCreator: a0412235
FID1-FID3 = Fiducial: Fiducial mark.  There is nothing to buy or mount.; SymbolCreator: codlsc
LBL1 = THT-14-423-10: Thermal Transfer Printable Labels, 0.650" W x 0.200" H - 10,000 per roll; Manufacturer: Brady; SymbolCreator: a0412235; CompType: Label
Logo1 = ESD_Susceptible: ESD Susceptible Symbol; SymbolCreator: a0412235
Logo2 = Pb-Free: SymbolCreator: a0412235
Logo3 = FCC_disclaimer: SymbolCreator: codlsc
Logo4 = CMP-0074769-1
ZZ1 = AssemblyNoteLabel: SymbolCreator: a0412235
ZZ2-ZZ4 = AssemblyNote: SymbolCreator: codlsc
